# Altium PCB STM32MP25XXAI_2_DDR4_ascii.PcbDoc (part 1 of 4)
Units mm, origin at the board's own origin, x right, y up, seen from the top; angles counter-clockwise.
Board outline 172 x 137 mm, 4 copper layers (Top Layer, Signal Layer 1, Signal Layer 2, Bottom Layer), stack 1.614 mm thick; 241 components, 153 nets, 1312 pads, 924 vias.
Unrouted connection lines stored in the file: 13.
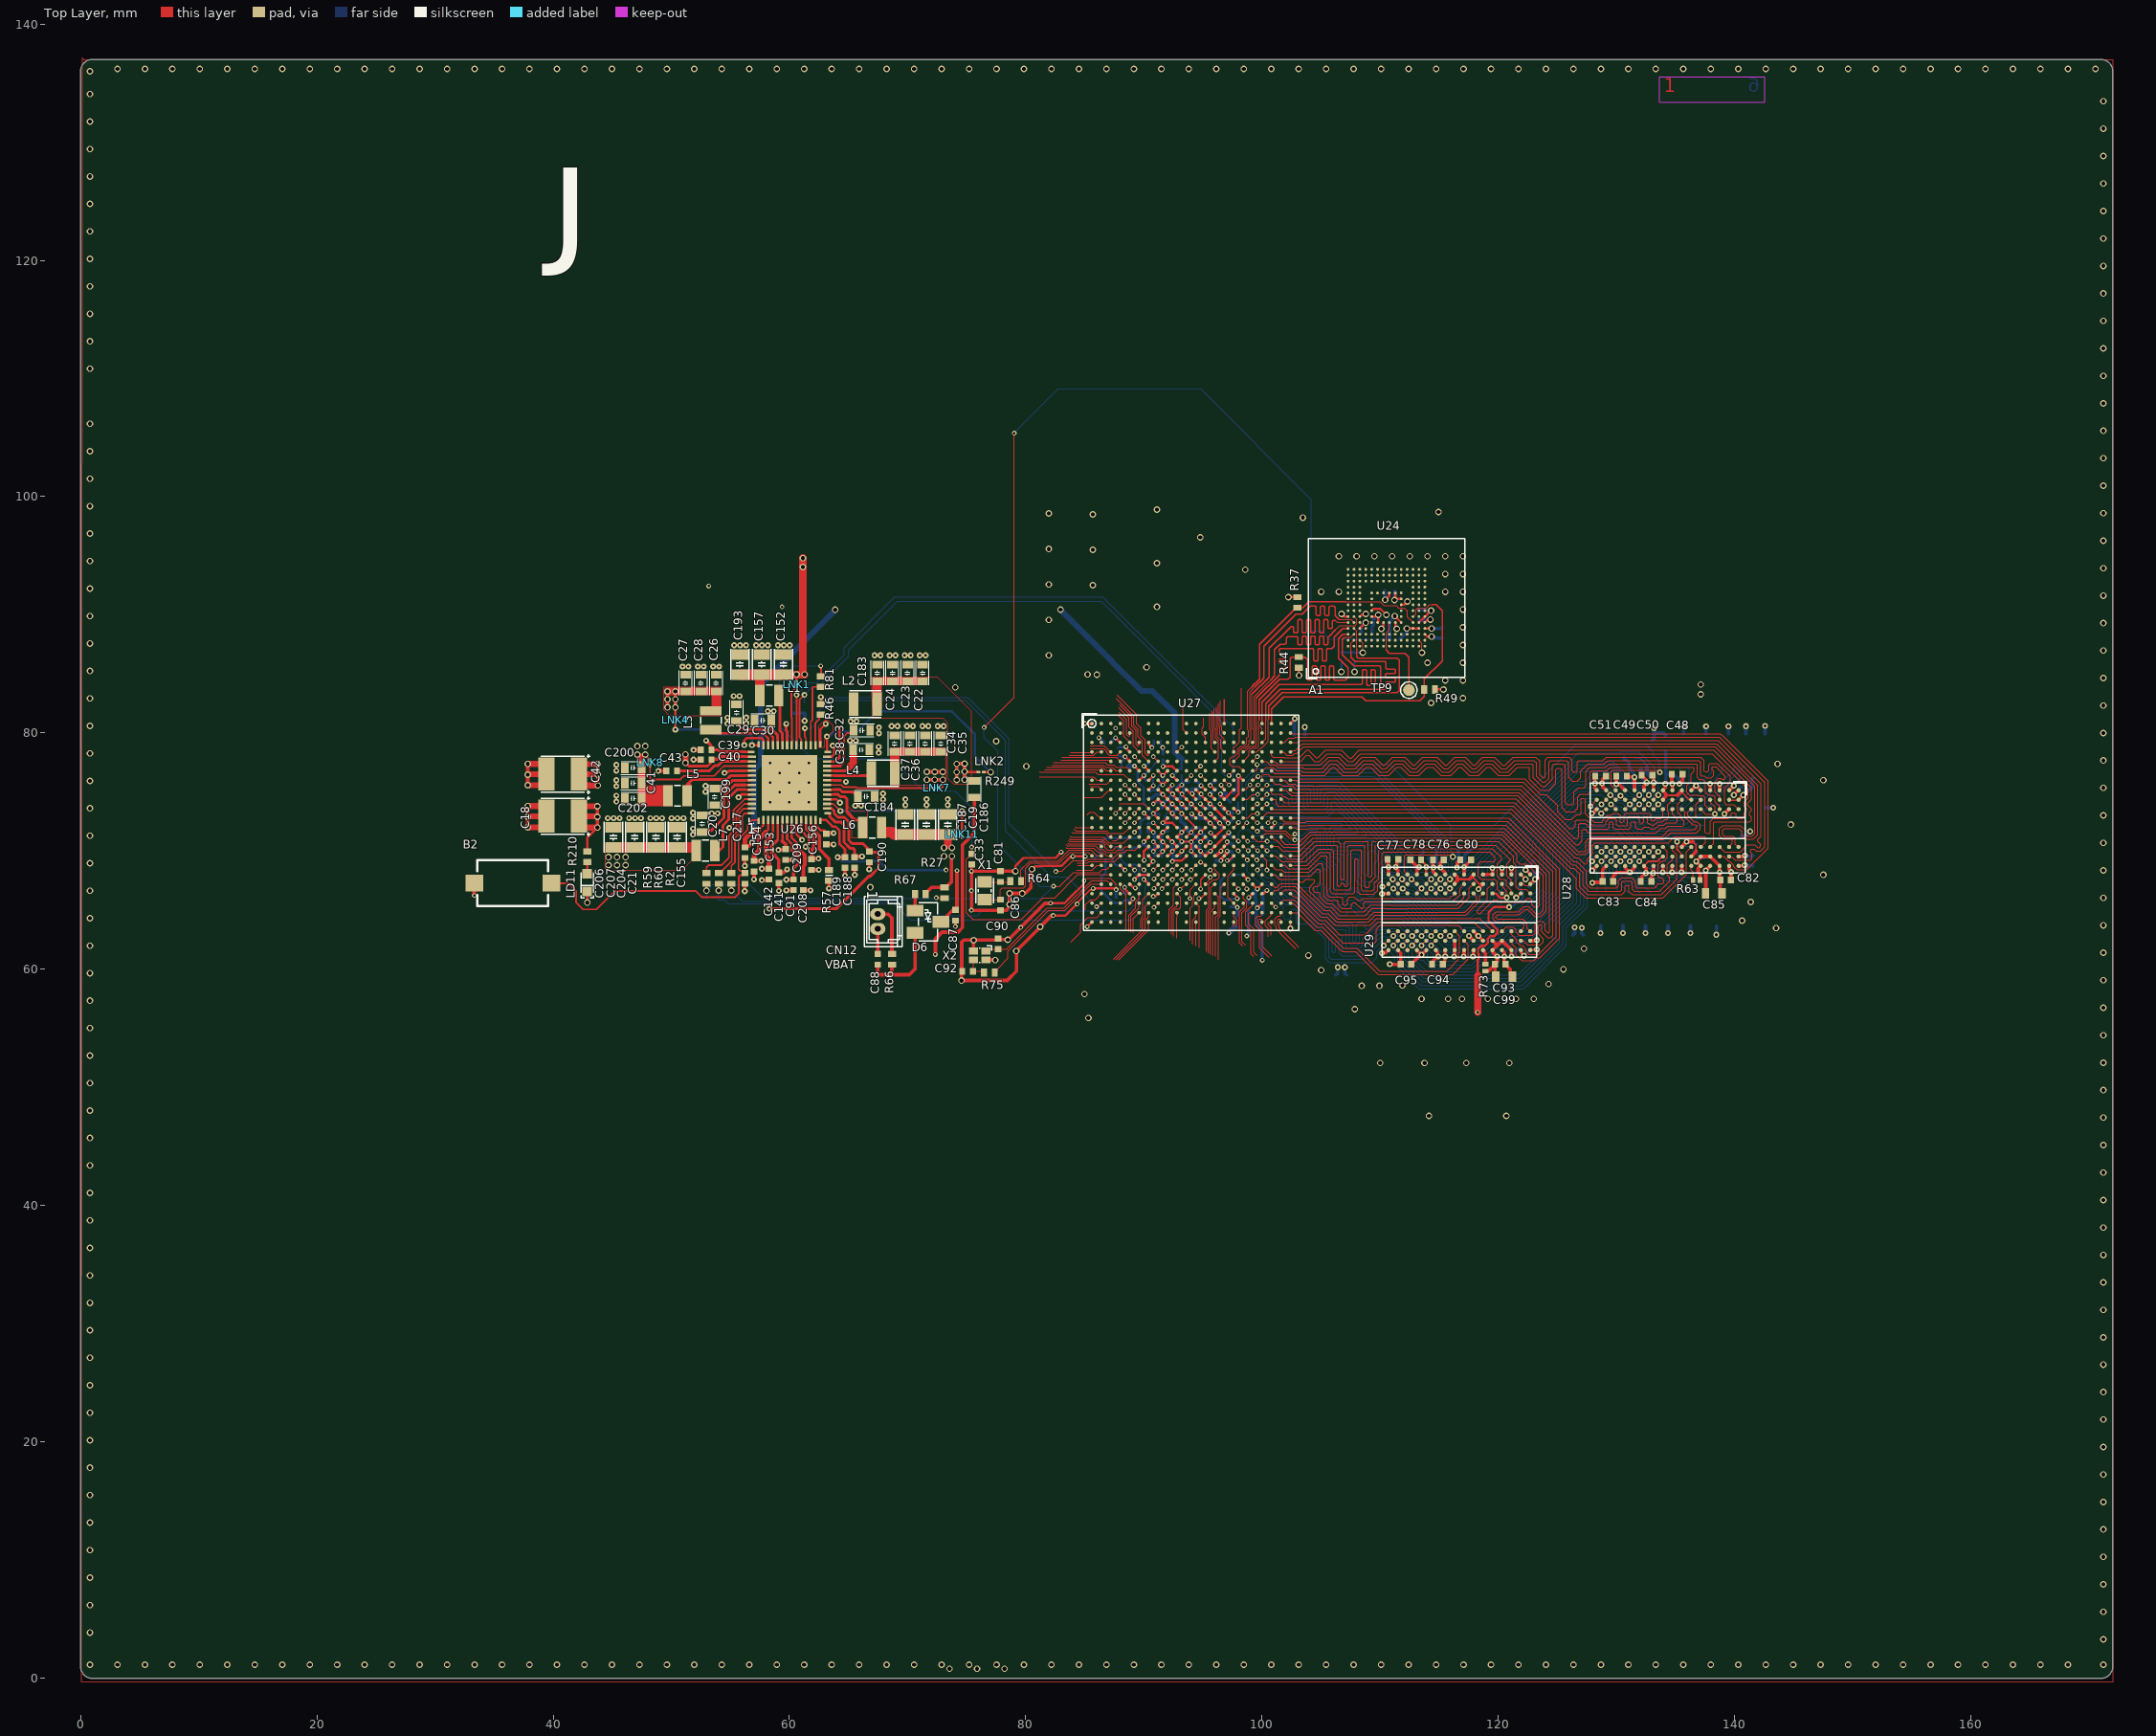
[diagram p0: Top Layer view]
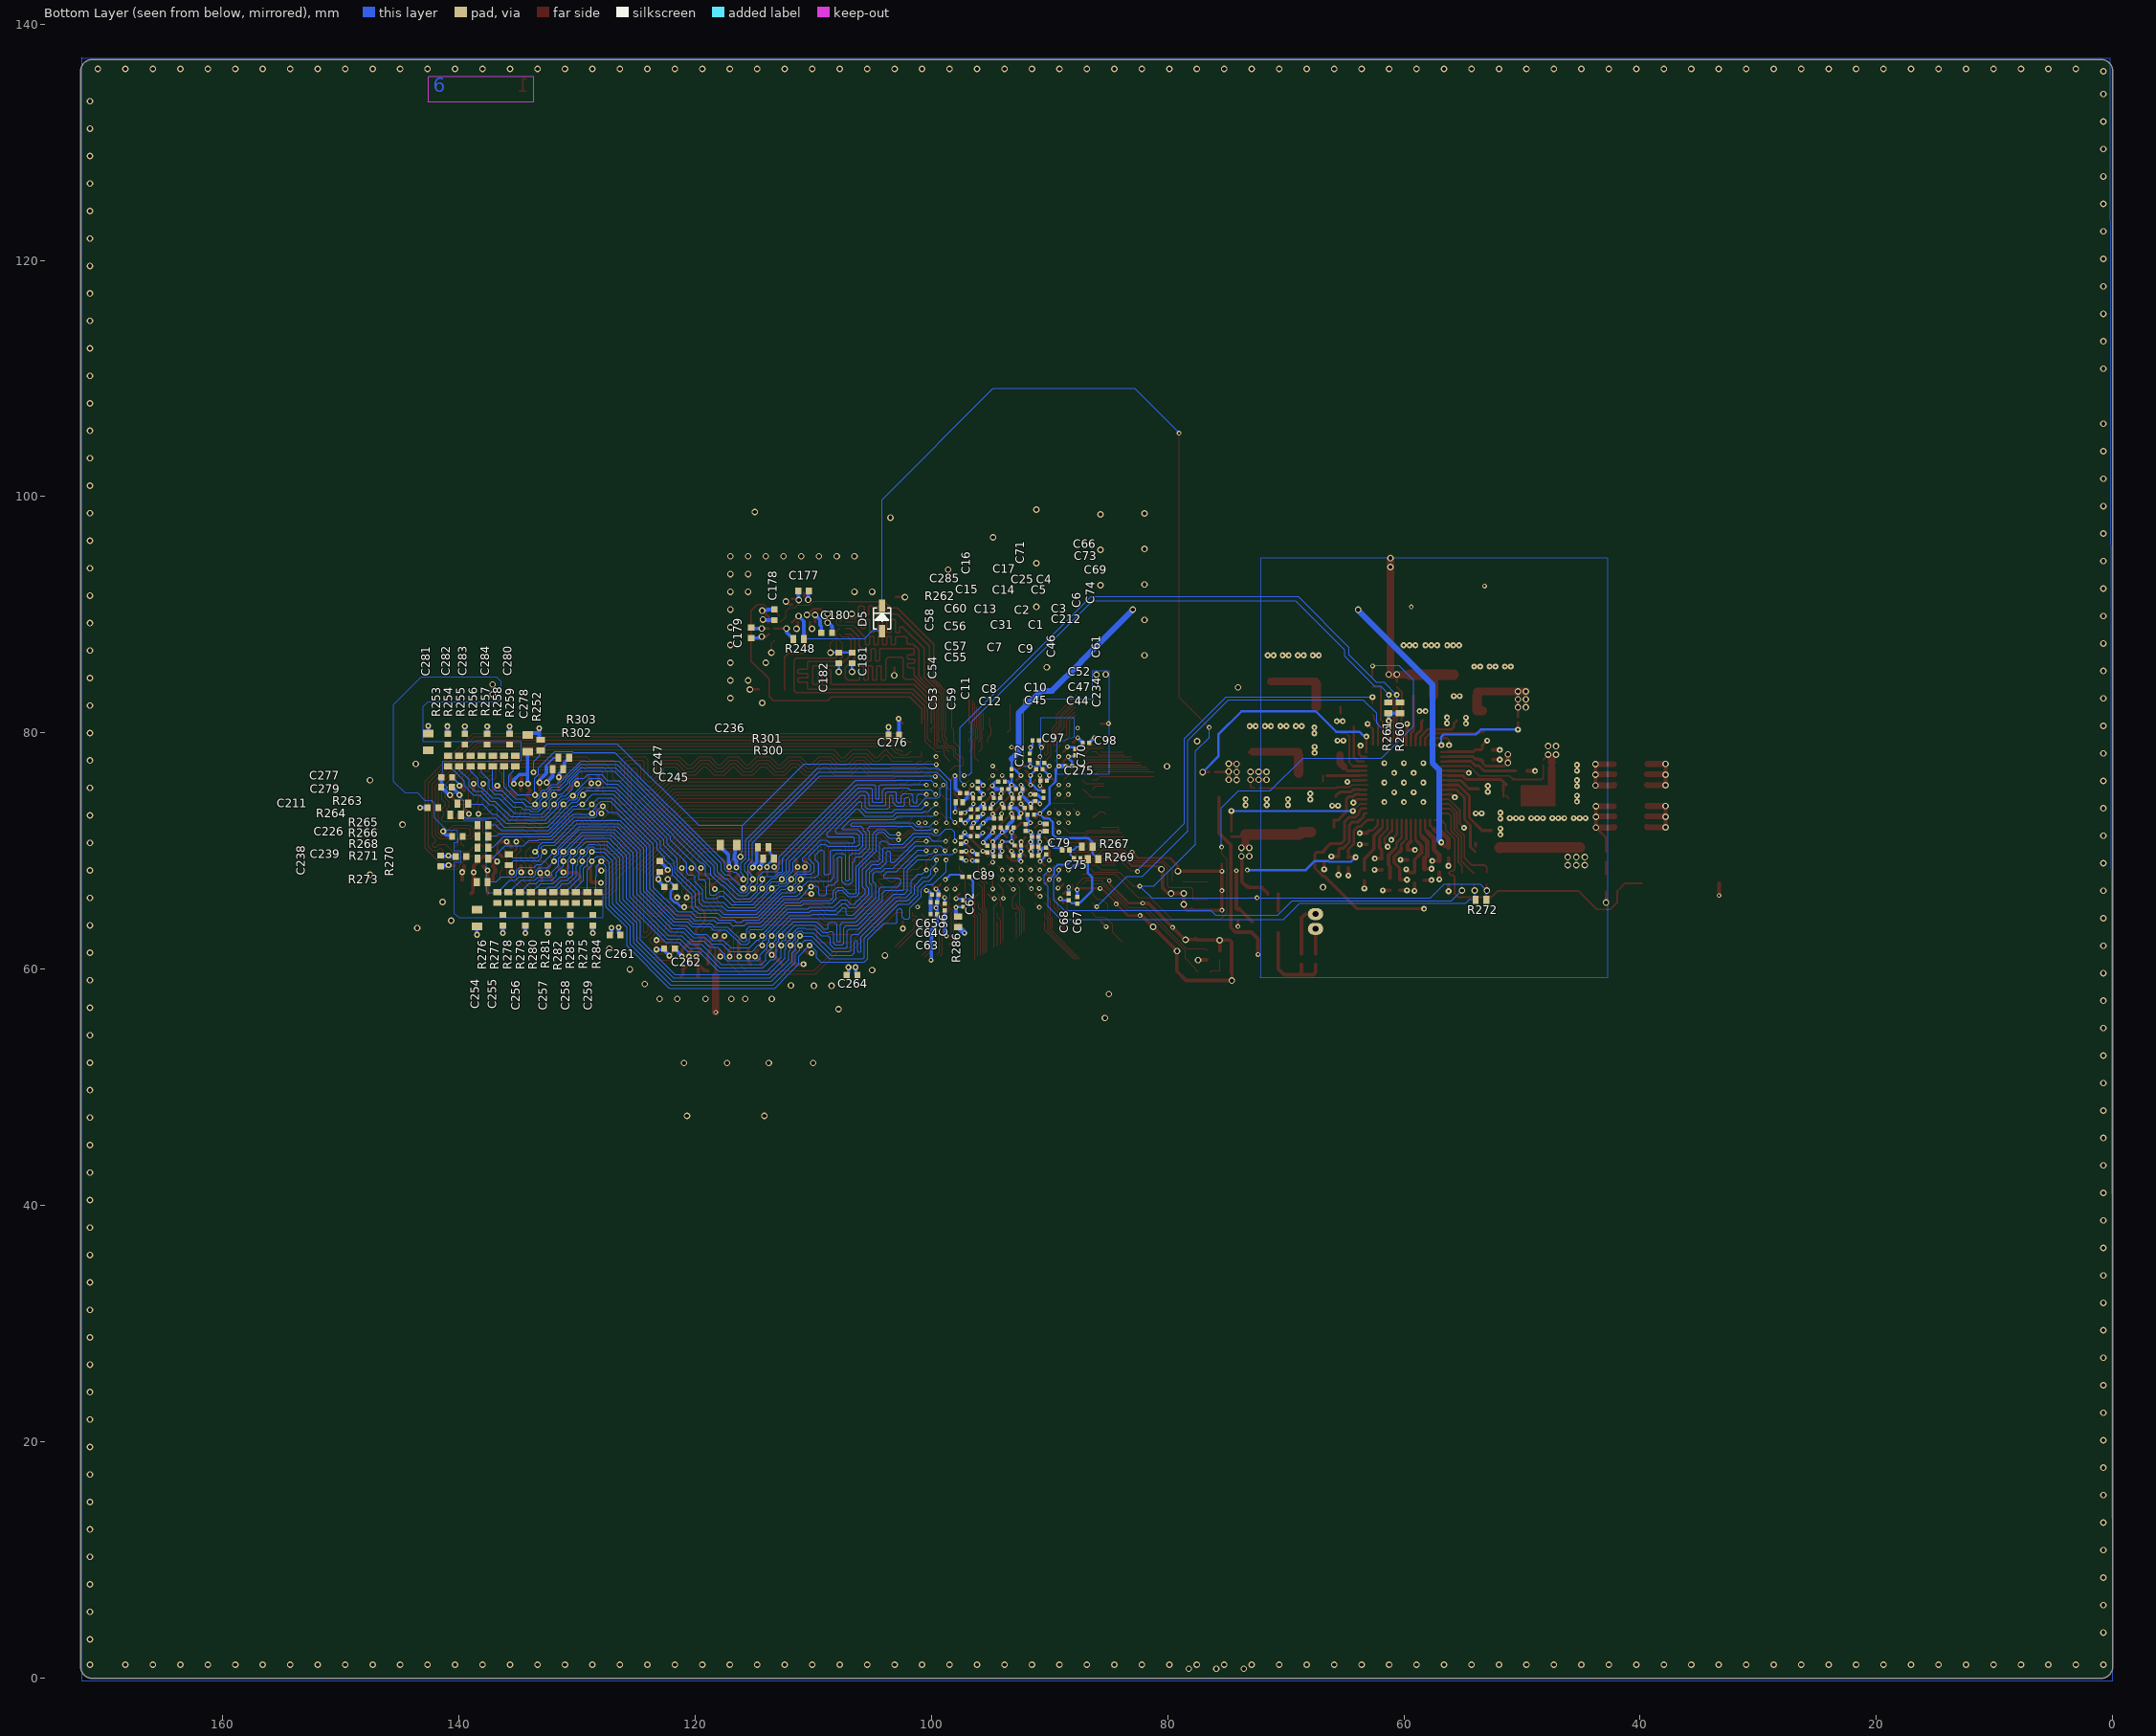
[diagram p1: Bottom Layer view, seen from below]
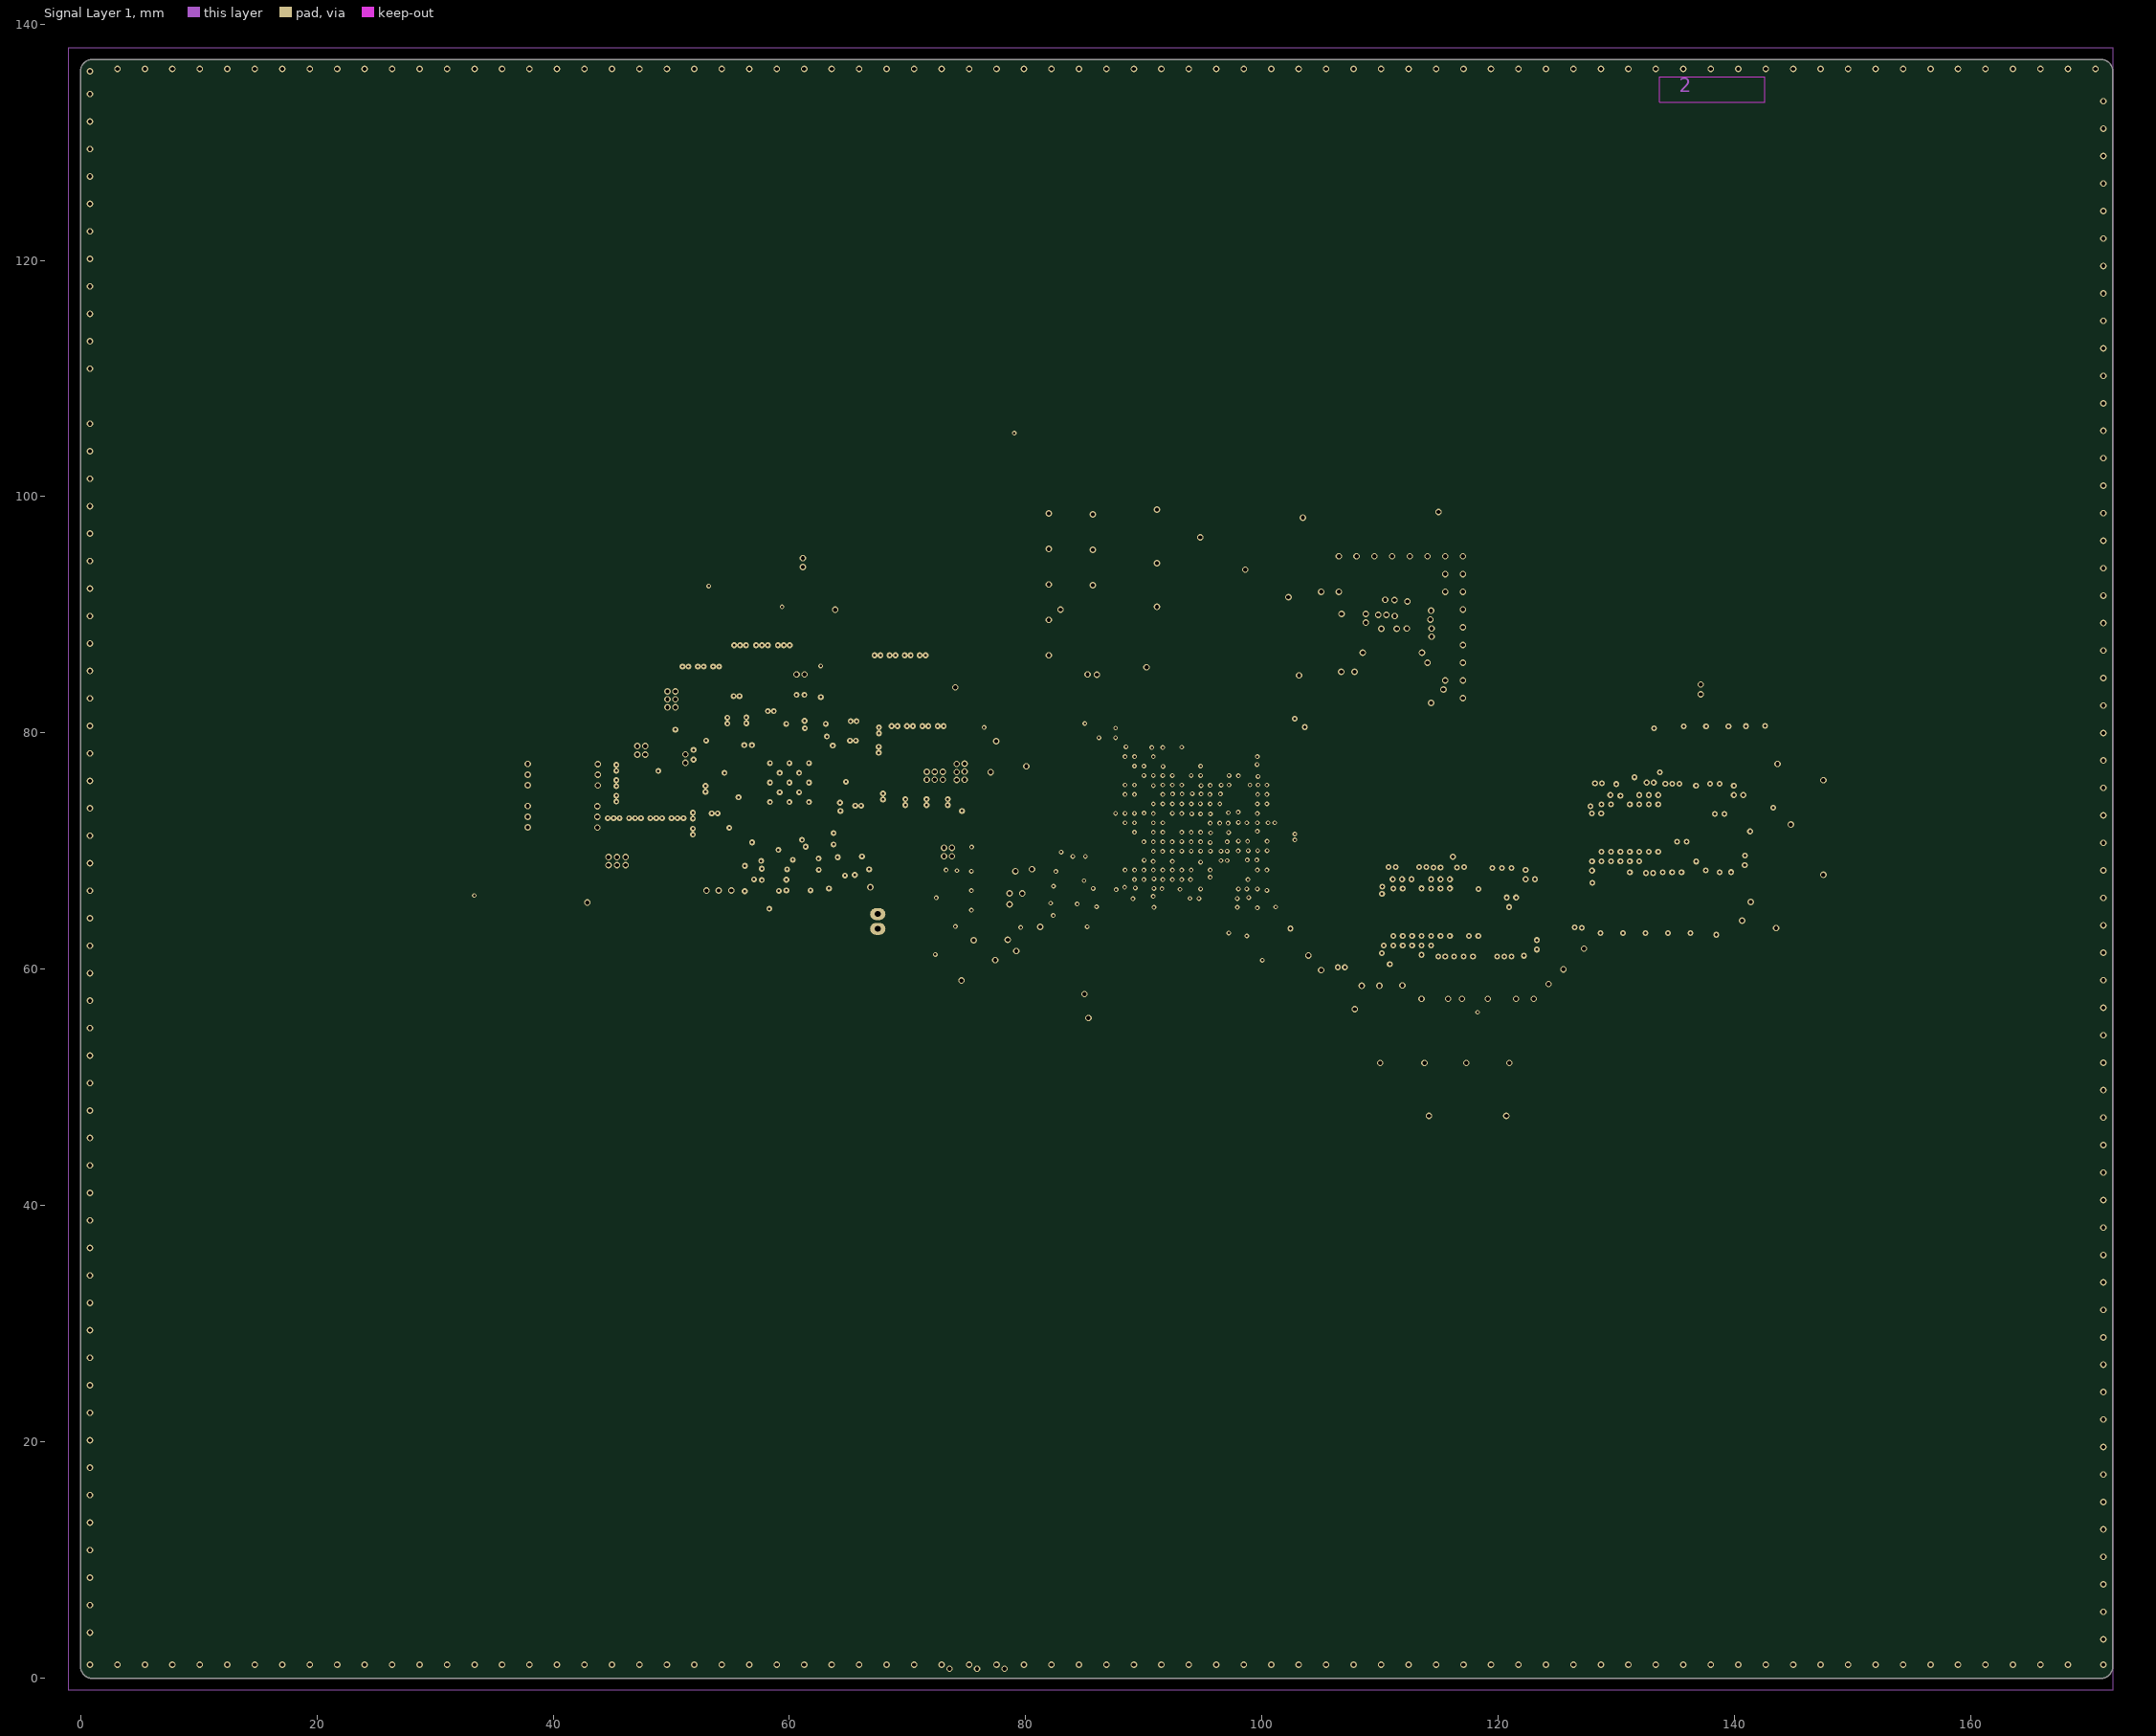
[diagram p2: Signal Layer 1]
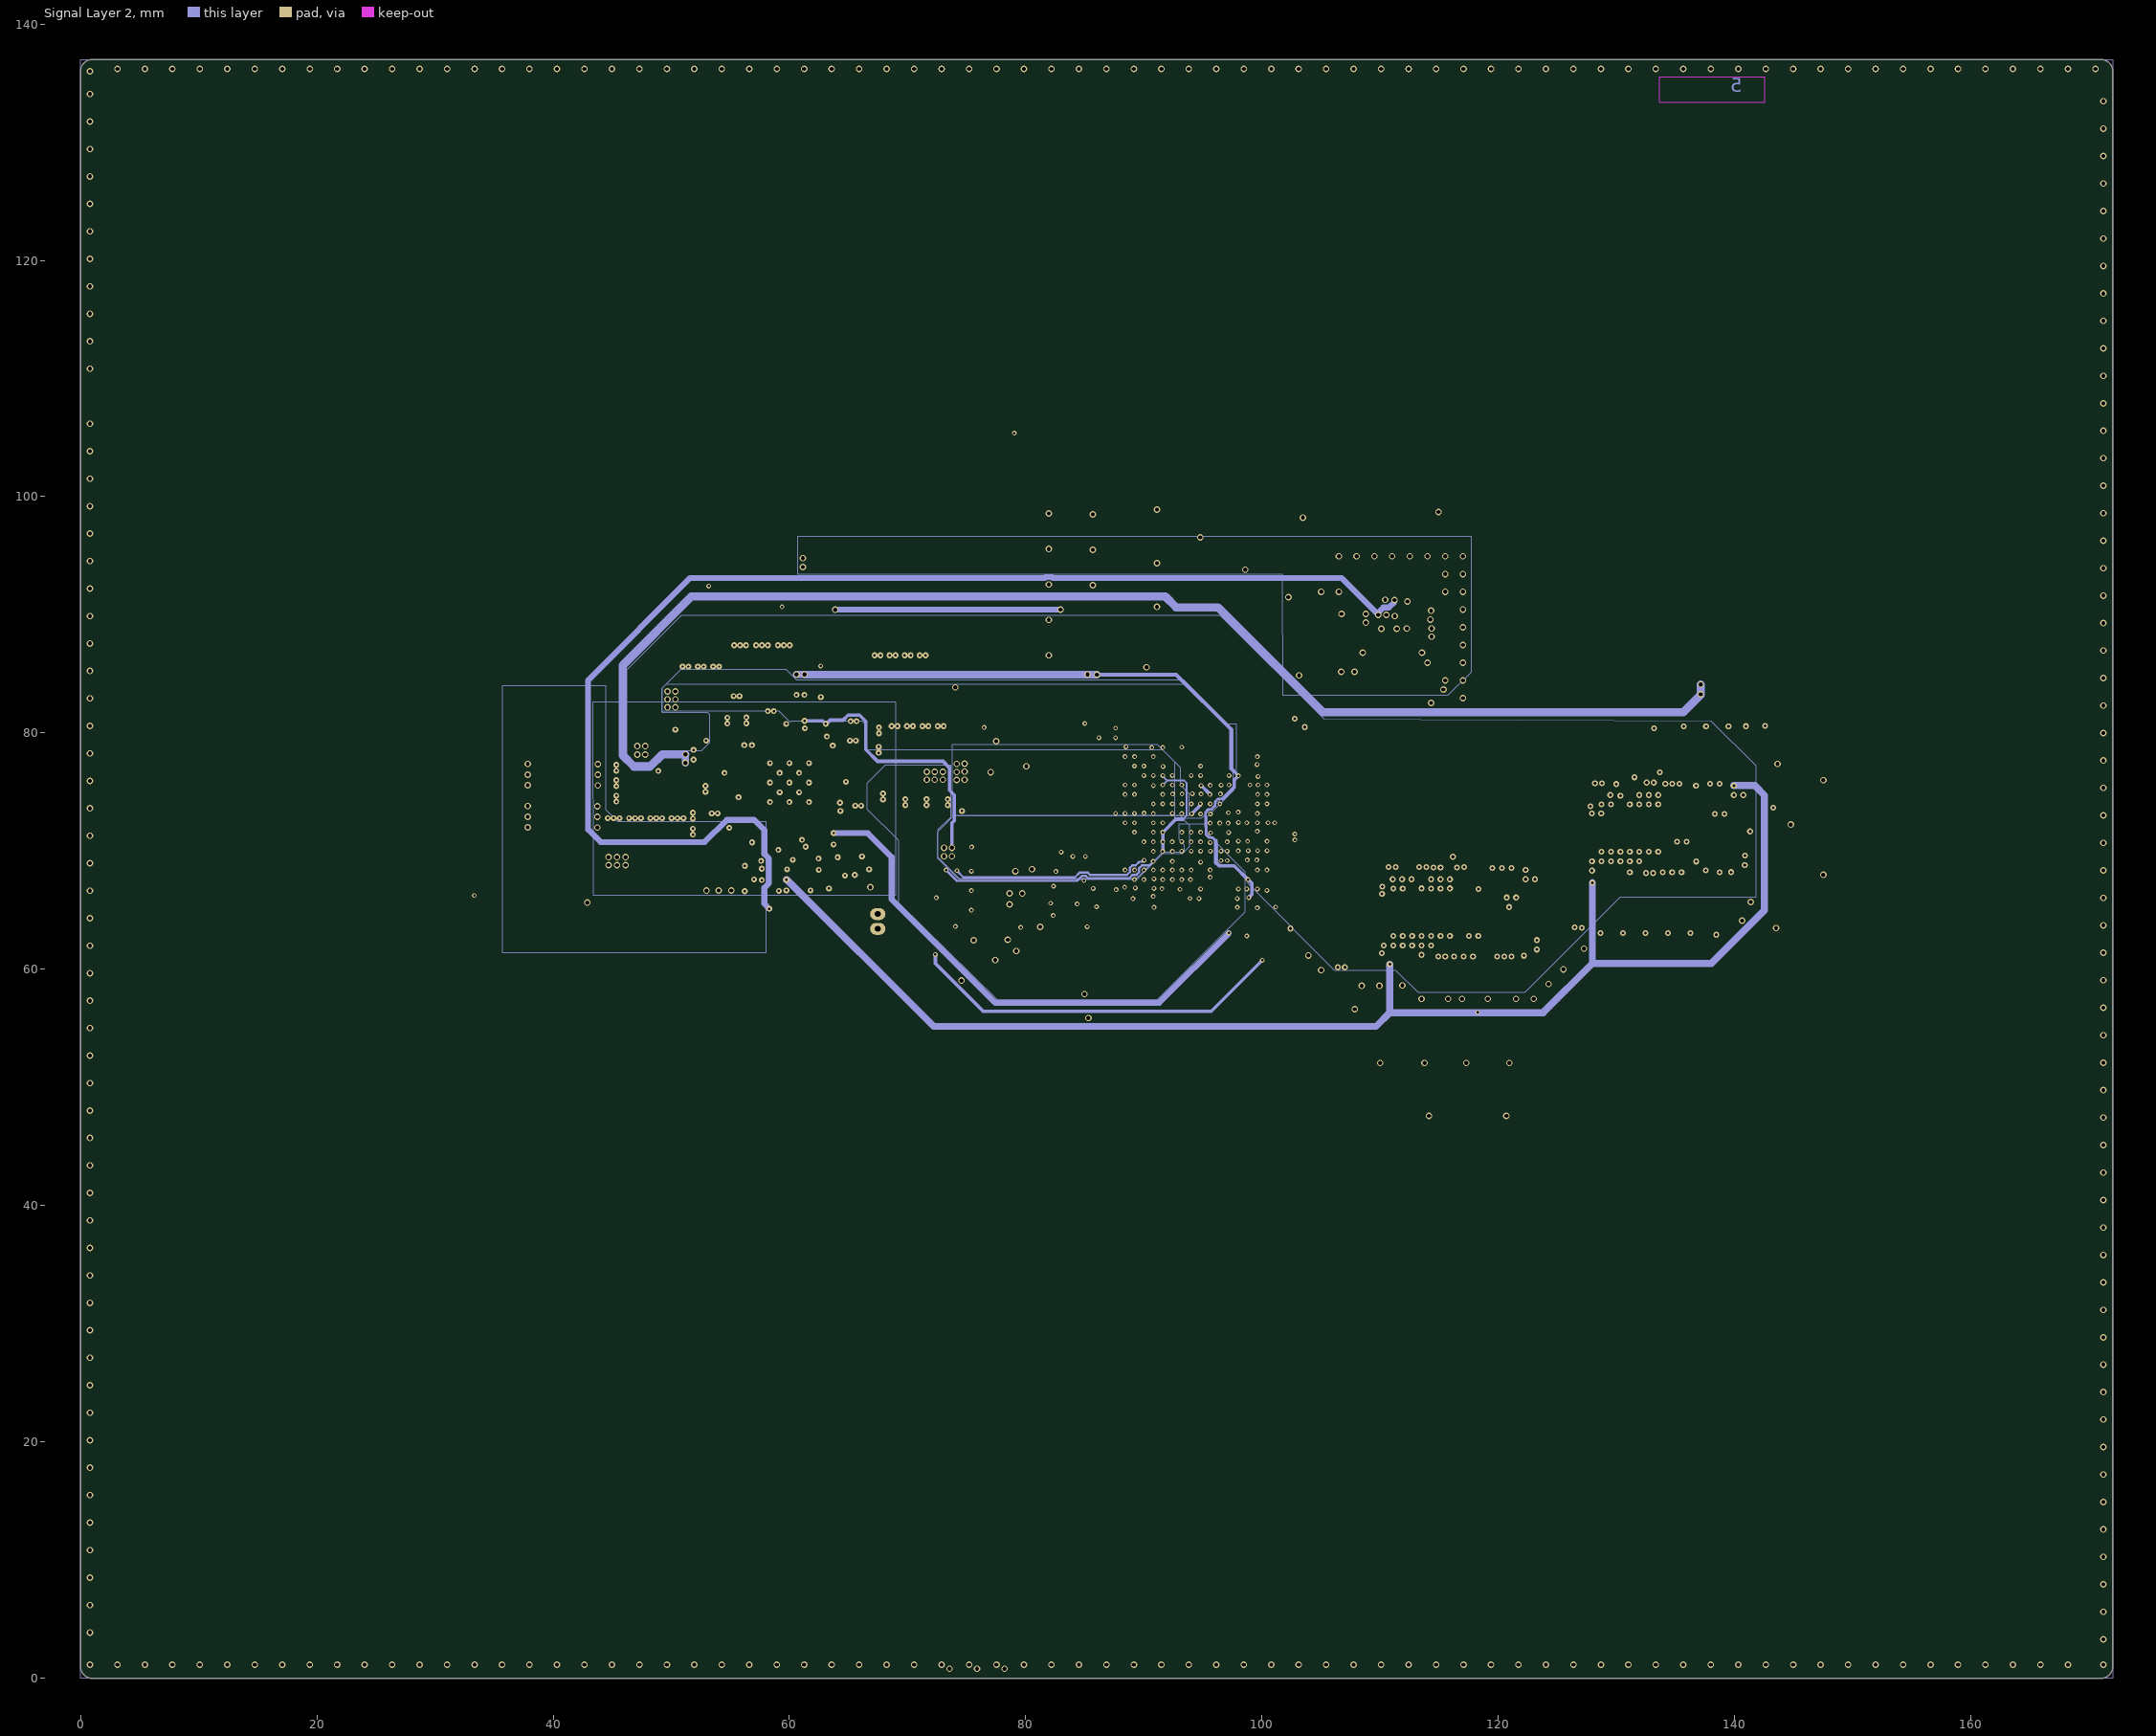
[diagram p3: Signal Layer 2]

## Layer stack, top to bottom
Top Solder: solder mask 0.025, Solder Resist, Dk 3.5
Top Layer: signal copper 0.037
Dielectric 1: prepreg 0.07, Dk 3.8
Signal Layer 1: signal copper 0.035
Dielectric 2: core 1.33, Dk 4.3
Signal Layer 2: signal copper 0.035
Dielectric 3: prepreg 0.07, Dk 3.8
Bottom Layer: signal copper 0.037
Bottom Solder: solder mask 0.025, Solder Resist, Dk 3.5

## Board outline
0,1 0,95 0,136 cw(c1,136) 1,137 171,137 cw(c171,136) 172,136 172,1 cw(c171,1) 171,0 1,0 cw(c1,1)

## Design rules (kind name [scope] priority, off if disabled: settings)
AssemblyTestPointUsage [All] p0: scope1count=1 scope1_0_kind=Board scope1_0_value=Board scope2count=1 scope2_0_kind=Board scope2_0_value=Board commentlength=0
AssemblyTestpoint [All] p0: scope1count=1 scope1_0_kind=Board scope1_0_value=Board scope2count=1 scope2_0_kind=Board scope2_0_value=Board commentlength=0
BoardOutlineClearance Silkscreen [All] p0 off: scope1count=1 scope1_0_kind=Board scope1_0_value=Board scope2count=1 scope2_0_kind=Board scope2_0_value=Board commentlength=90 gap=0 // Protel DXP Scope 1 Expression Was: OnLayer('Top Overlay') or OnLayer('Bottom Overlay')
BoardOutlineClearance [All] p0: scope1count=1 scope1_0_kind=Board scope1_0_value=Board scope2count=1 scope2_0_kind=Board scope2_0_value=Board commentlength=0 gap=0.5
BoardOutlineClearance Silkscreen [OnLayer('Top Overlay') or OnLayer('Bottom Overlay')] p1: gap=0 ignorepadtopadclearanceinfootprint=FALSE
BoardOutlineClearance [All] p2: gap=0.5 ignorepadtopadclearanceinfootprint=FALSE
Clearance Clearance_Default [All] p0: scope1count=1 scope1_0_kind=Board scope1_0_value=Board scope2count=1 scope2_0_kind=Board scope2_0_value=Board commentlength=0 gap=0.1
Clearance Clearance_Default [All] p1: gap=0.1 ignorepadtopadclearanceinfootprint=TRUE except(0: Arc-Hole Track-Hole SMDPad-Hole THPad-Hole Via-Hole Fill-Hole Poly-Hole Region-Hole Text-Hole; 0.09: Track-Track Track-SMDPad)
ComponentClearance [All] p0 off: scope1count=1 scope1_0_kind=Board scope1_0_value=Board scope2count=1 scope2_0_kind=Board scope2_0_value=Board commentlength=0 gap=0.2 collisioncheckmode=3
ComponentClearance [All] p1 off: gap=0.2 collisioncheckmode=3 verticalgap=0 showdistances=FALSE
DiffPairsRouting DiffPairsRouting_DDR_100R [All] p0 off: scope1count=1 scope1_0_kind=Board scope1_0_value=Board scope2count=1 scope2_0_kind=Board scope2_0_value=Board commentlength=78 // Protel DXP Scope 1 Expression Was: InDifferentialPairClass('DPC_DDR_100R')
DiffPairsRouting DiffPairsRouting_DDR_100R [InDifferentialPairClass('DPC_DDR_100R')] p1: maxlimit=0.16 minlimit=0.14 mostfreqgap=0.254 toplayer_mingap=0.16 toplayer_prefgap=0.16 toplayer_minwidth=0.09 toplayer_maxwidth=0.09 toplayer_prefwidth=0.09 bottomlayer_mingap=0.16 bottomlayer_prefgap=0.16 bottomlayer_minwidth=0.09 bottomlayer_maxwidth=0.09 bottomlayer_prefwidth=0.09 impedanceprofiledriven=TRUE impedanceprofileid={5106416E-43F8-41F8-8BCA-F68B3FB1C141} impedanceprofilevalue=100.000000 maxuncoupledlength=12.7
FabricationTestPointUsage [All] p0: scope1count=1 scope1_0_kind=Board scope1_0_value=Board scope2count=1 scope2_0_kind=Board scope2_0_value=Board commentlength=0 valid=0 allowmultiple=FALSE
FabricationTestpoint [All] p0: scope1count=1 scope1_0_kind=Board scope1_0_value=Board scope2count=1 scope2_0_kind=Board scope2_0_value=Board commentlength=0 side=3 testpointundercomponent=TRUE minsize=1.016 maxsize=2.54 preferedsize=1.524 minholesize=0 maxholesize=1.016 preferedholesize=0.813 testpointgrid=0.025
FanoutControl Fanout_Default [All] p0: scope1count=1 scope1_0_kind=Board scope1_0_value=Board scope2count=1 scope2_0_kind=Board scope2_0_value=Board commentlength=30 // Fanout_Default (Default Rule)
FanoutControl Fanout_Small [All] p0 off: scope1count=1 scope1_0_kind=Board scope1_0_value=Board scope2count=1 scope2_0_kind=Board scope2_0_value=Board commentlength=84 // Protel DXP Scope 1 Expression Was: (CompPinCount < 5)   Fanout_Small (Default Rule)
FanoutControl Fanout_SOIC [All] p0 off: scope1count=1 scope1_0_kind=Board scope1_0_value=Board scope2count=1 scope2_0_kind=Board scope2_0_value=Board commentlength=71 // Protel DXP Scope 1 Expression Was: IsSOIC   Fanout_SOIC (Default Rule)
FanoutControl Fanout_LCC [All] p0 off: scope1count=1 scope1_0_kind=Board scope1_0_value=Board scope2count=1 scope2_0_kind=Board scope2_0_value=Board commentlength=69 // Protel DXP Scope 1 Expression Was: IsLCC   Fanout_LCC (Default Rule)
FanoutControl Fanout_BGA [All] p0 off: scope1count=1 scope1_0_kind=Board scope1_0_value=Board scope2count=1 scope2_0_kind=Board scope2_0_value=Board commentlength=69 // Protel DXP Scope 1 Expression Was: IsBGA   Fanout_BGA (Default Rule)
FanoutControl Fanout_BGA [IsBGA] p1: bgadir=Out bgaviamode=Closest fanoutstyle=Auto fanoutdirection=Alternating viagrid=0.025 // Fanout_BGA (Default Rule)
FanoutControl Fanout_LCC [IsLCC] p2: bgadir=Out bgaviamode=Closest fanoutstyle=Auto fanoutdirection=Alternating viagrid=0.025 // Fanout_LCC (Default Rule)
FanoutControl Fanout_SOIC [IsSOIC] p3: bgadir=Out bgaviamode=Closest fanoutstyle=Auto fanoutdirection=Alternating viagrid=0.025 // Fanout_SOIC (Default Rule)
FanoutControl Fanout_Small [(CompPinCount < 5)] p4: bgadir=Out bgaviamode=Closest fanoutstyle=Auto fanoutdirection=OutThenIn viagrid=0.025 // Fanout_Small (Default Rule)
FanoutControl Fanout_Default [All] p5: bgadir=Out bgaviamode=Closest fanoutstyle=Auto fanoutdirection=Alternating viagrid=0.025 // Fanout_Default (Default Rule)
Height [All] p0: scope1count=1 scope1_0_kind=Board scope1_0_value=Board scope2count=1 scope2_0_kind=Board scope2_0_value=Board commentlength=0
HoleSize [All] p0: scope1count=1 scope1_0_kind=Board scope1_0_value=Board scope2count=1 scope2_0_kind=Board scope2_0_value=Board commentlength=0 absolutevalues=TRUE maxlimit=10 minlimit=0.025 maxpercent=80.000 minpercent=20.000
HoleSize [All] p1: absolutevalues=TRUE maxlimit=10 minlimit=0.025 maxpercent=80.000 minpercent=20.000
HoleToHoleClearance [All] p0: scope1count=1 scope1_0_kind=Board scope1_0_value=Board scope2count=1 scope2_0_kind=Board scope2_0_value=Board commentlength=0
HoleToHoleClearance [All] p1: gap=0.25 allowstackedmicrovias=TRUE
LayerPairs [All] p0: scope1count=1 scope1_0_kind=Board scope1_0_value=Board scope2count=1 scope2_0_kind=Board scope2_0_value=Board commentlength=0 enforce=TRUE
MinimumSolderMaskSliver [All] p0: scope1count=1 scope1_0_kind=Board scope1_0_value=Board scope2count=1 scope2_0_kind=Board scope2_0_value=Board commentlength=0
MinimumSolderMaskSliver [All] p1: minsoldermaskwidth=0.07
NetAntennae [All] p0: scope1count=1 scope1_0_kind=Board scope1_0_value=Board scope2count=1 scope2_0_kind=Board scope2_0_value=Board commentlength=0
PasteMaskExpansion [All] p0: scope1count=1 scope1_0_kind=Board scope1_0_value=Board scope2count=1 scope2_0_kind=Board scope2_0_value=Board commentlength=0 expansion=0
PlaneClearance [All] p0: scope1count=1 scope1_0_kind=Board scope1_0_value=Board scope2count=1 scope2_0_kind=Board scope2_0_value=Board commentlength=0 clearance=0.508
PlaneConnect [All] p0: scope1count=1 scope1_0_kind=Board scope1_0_value=Board scope2count=1 scope2_0_kind=Board scope2_0_value=Board commentlength=0 planeconnectstyle=Direct reliefexpansion=0.508 reliefentries=4 reliefconductorwidth=0.21 reliefairgap=0.21
PlaneConnect [All] p1: planeconnectstyle=Direct reliefexpansion=0.508 reliefentries=4 reliefconductorwidth=0.21 reliefairgap=0.21
PolygonConnect PolygonConnect_Default [All] p0: scope1count=1 scope1_0_kind=Board scope1_0_value=Board scope2count=1 scope2_0_kind=Board scope2_0_value=Board commentlength=0 connectstyle=Direct reliefconductorwidth=0.25 reliefentries=4 polygonreliefangle="90 Angle"
PolygonConnect PolygonConnect_Default [All] p1: connectstyle=Direct reliefconductorwidth=0.25 reliefentries=4 polygonreliefangle="90 Angle" airgapwidth=0.25
RoutingCorners [All] p0: scope1count=1 scope1_0_kind=Board scope1_0_value=Board scope2count=1 scope2_0_kind=Board scope2_0_value=Board commentlength=0 cornerstyle=45-Degree minsetback=2.54 maxsetback=2.54
RoutingLayers [All] p0: scope1count=1 scope1_0_kind=Board scope1_0_value=Board scope2count=1 scope2_0_kind=Board scope2_0_value=Board commentlength=0 top layer=Automatic mid layer 1=Automatic mid layer 4=Automatic bottom layer=Automatic
RoutingPriority [All] p0: scope1count=1 scope1_0_kind=Board scope1_0_value=Board scope2count=1 scope2_0_kind=Board scope2_0_value=Board commentlength=0
RoutingTopology [All] p0: scope1count=1 scope1_0_kind=Board scope1_0_value=Board scope2count=1 scope2_0_kind=Board scope2_0_value=Board commentlength=0 topology=Shortest
RoutingVias RoutingVias_Default [All] p0: scope1count=1 scope1_0_kind=Board scope1_0_value=Board scope2count=1 scope2_0_kind=Board scope2_0_value=Board commentlength=0 holewidth=0.15 width=0.4 viastyle="Through Hole" minholewidth=0.15 minwidth=0.4 maxholewidth=0.35 maxwidth=0.6
RoutingVias RoutingVias_Default [All] p1: holewidth=0.15 width=0.4 viastyle="Through Hole" minholewidth=0.15 minwidth=0.4 maxholewidth=0.35 maxwidth=0.6 viatemplateguid#1={BF886351-5902-4D8E-87A9-DD407FAE4AFA} viatemplateguid#2={A479BBDC-94B7-4D18-B59D-B7A18B767B5F} viatemplateguid#3={564DD7E2-F718-4BCE-8A99-5417C9FECCB6} viatemplateguid#4={BB8F4C89-420F-4EBC-9772-FD82009DE81A} viatemplateguid#5={3FF096CA-B7A5-4E0B-A50A-8B2CD18CCC19} viatemplatename#1=v50h25m30mx30 viatemplatename#2=v55h35m40mx40 viatemplatename#3=v40h20m0mx0 viatemplatename#4=v40h20m25mx25 viatemplatename#5=v50h25m0mx0
ShortCircuit ShortCircuit_Link200 [All] p0: scope1count=1 scope1_0_kind=PadClass scope1_0_value=PC_LINK200 scope2count=1 scope2_0_kind=Board scope2_0_value=Board commentlength=0 allowed=TRUE
ShortCircuit ShortCircuit_Link200 [InPadClass('PC_LINK200')] p1: allowed=TRUE
SilkToBoardRegionClearance [All] p0: scope1count=1 scope1_0_kind=Board scope1_0_value=Board scope2count=1 scope2_0_kind=Board scope2_0_value=Board commentlength=0
SilkToSilkClearance [All] p0: scope1count=1 scope1_0_kind=Board scope1_0_value=Board scope2count=1 scope2_0_kind=Board scope2_0_value=Board commentlength=0
SilkToSilkClearance [All] p1: silktosilkclearance=0.2
SilkToSolderMaskClearance [All] p0 off: scope1count=1 scope1_0_kind=Board scope1_0_value=Board scope2count=1 scope2_0_kind=Board scope2_0_value=Board commentlength=44 // Protel DXP Scope 1 Expression Was: IsPad
SilkToSolderMaskClearance [IsPad] p1: minsilkscreentomaskgap=0.015 clearancetoexposedcopper=TRUE
SolderMaskExpansion [All] p0: scope1count=1 scope1_0_kind=Board scope1_0_value=Board scope2count=1 scope2_0_kind=Board scope2_0_value=Board commentlength=0 expansion=0.1
SolderMaskExpansion [All] p1: expansion=0.1 istentingtop=FALSE
UnRoutedNet [All] p0: scope1count=1 scope1_0_kind=Board scope1_0_value=Board scope2count=1 scope2_0_kind=Board scope2_0_value=Board commentlength=0
UnpouredPolygon [All] p0: scope1count=1 scope1_0_kind=Board scope1_0_value=Board scope2count=1 scope2_0_kind=Board scope2_0_value=Board commentlength=0
ViasUnderSMD [All] p0: scope1count=1 scope1_0_kind=PadClass scope1_0_value=PC_VIAS-IN-PAD_OK scope2count=1 scope2_0_kind=Board scope2_0_value=Board commentlength=0 allowed=TRUE
ViasUnderSMD [InPadClass('PC_VIAS-IN-PAD_OK')] p1: allowed=TRUE
Width Width_Default [All] p0: scope1count=1 scope1_0_kind=NetClass scope1_0_value="All Nets" scope2count=1 scope2_0_kind=Board scope2_0_value=Board commentlength=0 maxlimit=10 minlimit=0.09 preferedwidth=0.1
Width Width_Default [InNetClass('All Nets')] p1: maxlimit=10 minlimit=0.09 preferedwidth=0.1
16 further rules are at their usual default settings.

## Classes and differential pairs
differential pair DDR_DQS3: +DDR_DQS3_P -DDR_DQS3_N
differential pair DDR_DQS2: +DDR_DQS2_P -DDR_DQS2_N
differential pair DDR_DQS1: +DDR_DQS1_P -DDR_DQS1_N
differential pair DDR_DQS0: +DDR_DQS0_P -DDR_DQS0_N
differential pair " ": +DDR_CLK_P -DDR_CLK_N

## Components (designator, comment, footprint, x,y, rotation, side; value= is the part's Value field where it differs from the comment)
B2 "SW_PUSH_SMD_2P" SWI_WE_434121025816 36.59,67.295 r0 top
C1 "Capacitor" C0201_MURATA_GRM033_H0P3 92.825,72.825 r0 bottom
C2 "Capacitor" C0201_MURATA_GRM033_H0P3 93.601,73.65 r180 bottom
C3 "Capacitor" C0201_MURATA_GRM033_H0P3 91.825,73.65 r180 bottom
C4 "Capacitor" C0201_MURATA_GRM033_H0P3 92.55,75.25 r0 bottom
C5 "Capacitor" C0201_MURATA_GRM033_H0P3 92.826,74.475 r180 bottom
C6 "Capacitor" C0201_MURATA_GRM033_H0P3 91.2,74.525 r270 bottom
C7 "Capacitor" C0201_MURATA_GRM033_H0P3 94.4,72 r0 bottom
C8 "Capacitor" C0201_MURATA_GRM033_H0P3 94.425,70.425 r180 bottom
C9 "Capacitor" C0201_MURATA_GRM033_H0P3 93.3,72 r180 bottom
C10 "Capacitor" C0201_MURATA_GRM033_H0P3 92.675,70.48 r0 bottom
C11 "Capacitor" C0201_MURATA_GRM033_H0P3 95.25,70.175 r270 bottom
C12 "Capacitor" C0201_MURATA_GRM033_H0P3 94.425,69.575 r180 bottom
C13 "Capacitor" C0201_MURATA_GRM033_H0P3 95.232,73.625 r0 bottom
C14 "Capacitor" C0201_MURATA_GRM033_H0P3 94.425,74.48 r180 bottom
C15 "Capacitor" C0201_MURATA_GRM033_H0P3 96.175,74.475 r180 bottom
C16 "Capacitor" C0201_MURATA_GRM033_H0P3 96.075,75.6 r90 bottom
C17 "Capacitor" C0201_MURATA_GRM033_H0P3 94.05,75.875 r0 bottom
C18 "Cap_POL_TANA" CPOL_TCJ-B_1210_H210 40.812,72.961 r180 top
C19 "Capacitor" C0805 71.6,72.25 r270 top
C20 "Capacitor" C0603 52.6,72.325 r270 top
C21 "Capacitor" C0805 50.5,71.173 r270 top
C22 "Capacitor" C0603 71.275,85.075 r270 top
C23 "Capacitor" C0603 70,85.075 r270 top
C24 "Capacitor" C0603 68.725,85.075 r270 top
C25 "Capacitor" C0201_MURATA_GRM033_H0P3 93.75,75.25 r0 bottom
C26 "Capacitor" C0603 53.8,84.225 r270 top
C27 "Capacitor" C0603 51.2,84.225 r270 top
C28 "Capacitor" C0603 52.5,84.225 r270 top
C29 "Capacitor" C0603 55.525,81.725 r270 top
C30 "Capacitor" C0603 57.75,81.075 r0 top
C31 "Capacitor" C0201_MURATA_GRM033_H0P3 94.4,72.775 r180 bottom
C32 "Capacitor" C0603 66.125,80.225 r180 top
C33 "Capacitor" C0402 75.425,69.325 r90 top
C34 "Capacitor" C0603 71.5,79.1 r270 top
C35 "Capacitor" C0603 72.8,79.1 r270 top
C36 "Capacitor" C0603 70.2,79.1 r270 top
C37 "Capacitor" C0603 68.9,79.1 r270 top
C38 "Capacitor" C0603 66.075,78.575 r180 top
C39 "Capacitor" C0402 52.945,78.575 r0 top
C40 "Capacitor" C0402 52.945,77.75 r0 top
C41 "Capacitor" C0603 46.775,75.75 r0 top
C42 "Cap_POL_TANA" CPOL_TCJ-B_1210_H210 40.812,76.523 r180 top
C43 "Capacitor" C0402 50.035,76.8 r0 top
C44 "Capacitor" C0201_MURATA_GRM033_H0P3 91.2,69.6 r180 bottom
C45 "Capacitor" C0201_MURATA_GRM033_H0P3 92.8,69.6 r0 bottom
C46 "Capacitor" C0201_MURATA_GRM033_H0P3 92.025,72 r270 bottom
C47 "Capacitor" C0201_MURATA_GRM033_H0P3 91.2,70.388 r180 bottom
C48 "Capacitor" C0402 135.125,76.5 r0 top
C49 "Capacitor" C0402 130.425,76.35 r0 top
C50 "Capacitor" C0402 132.575,76.425 r180 top
C51 "Capacitor" C0402 128.65,76.35 r0 top
C52 "Capacitor" C0201_MURATA_GRM033_H0P3 91.2,71.2 r0 bottom
C53 "Capacitor" C0201_MURATA_GRM033_H0P3 97.45,69.675 r270 bottom
C54 "Capacitor" C0201_MURATA_GRM033_H0P3 97.475,70.9 r90 bottom
C55 "Capacitor" C0201_MURATA_GRM033_H0P3 96.375,71.275 r180 bottom
C56 "Capacitor" C0201_MURATA_GRM033_H0P3 96.349,72.875 r180 bottom
C57 "Capacitor" C0201_MURATA_GRM033_H0P3 96.301,71.974 r0 bottom
C58 "Capacitor" C0201_MURATA_GRM033_H0P3 97.5,72.925 r90 bottom
C59 "Capacitor" C0201_MURATA_GRM033_H0P3 96.1,69.45 r90 bottom
C60 "Capacitor" C0201_MURATA_GRM033_H0P3 96.356,73.524 r0 bottom
C61 "Capacitor" C0201_H0P5 90.317,71.988 r90 bottom
C62 "Capacitor" C0201_MURATA_GRM033_H0P3 97.3,65.575 r270 bottom
C63 "Capacitor" C0201_MURATA_GRM033_H0P3 99.775,64.675 r180 bottom
C64 "Capacitor" C0201_MURATA_GRM033_H0P3 99.775,65.675 r180 bottom
C65 "Capacitor" C0201_MURATA_GRM033_H0P3 99.65,66.325 r180 bottom
C66 "Capacitor" C0201_MURATA_GRM033_H0P3 90.7,77.475 r180 bottom
C67 "Capacitor" C0201_MURATA_GRM033_H0P3 87.63,65.845 r270 bottom
C68 "Capacitor" C0201_MURATA_GRM033_H0P3 88.375,66.125 r270 bottom
C69 "Capacitor" C0201_MURATA_GRM033_H0P3 90.48,75.97 r0 bottom
C70 "Capacitor" C0201_MURATA_GRM033_H0P3 87.8,78.375 r90 bottom
C71 "Capacitor" C0201_MURATA_GRM033_H0P3 93.201,76.675 r90 bottom
C72 "Capacitor" C0201_MURATA_GRM033_H0P3 91.675,77.975 r270 bottom
C73 "Capacitor" C0201_MURATA_GRM033_H0P3 90.85,76.925 r0 bottom
C74 "Capacitor" C0201_MURATA_GRM033_H0P3 90.5,74.775 r90 bottom
C75 "Capacitor" C0201_MURATA_GRM033_H0P3 87.65,69.425 r0 bottom
C76 "Capacitor" C0402 114.925,69.275 r180 top
C77 "Capacitor" C0402 111.075,69.3 r0 top
C78 "Capacitor" C0402 113,69.275 r0 top
C79 "Capacitor" C0201_H0P5 88.6,70.125 r180 bottom
C80 "Capacitor" C0402 117.225,69.275 r180 top
C81 "Capacitor" C0402 77.85,67.85 r90 top
C82 "Capacitor" C0402 139.225,67.55 r0 top
C83 "Capacitor" C0402 129.275,67.45 r180 top
C84 "Capacitor" C0402 132.5,67.45 r180 top
C85 "Capacitor" C0603 138.225,66.425 r180 top
C86 "Capacitor" C0402 77.85,65.45 r270 top
C87 "" C0402 74.05,64.575 r90 top
C88 "Capacitor" C0402 67.475,60.85 r270 top
C89 "Capacitor" C0201_MURATA_GRM033_H0P3 97.075,67.825 r0 bottom
C90 "Capacitor" C0402 77.65,62.15 r270 top
C91 "Capacitor" C0402 60.345,67.16 r270 top
C92 "Capacitor" C0402 75.075,59.825 r180 top
C93 "Capacitor" C0402 120.15,60.425 r0 top
C94 "Capacitor" C0402 114.844,60.422 r180 top
C95 "Capacitor" C0402 112.175,60.425 r180 top
C96 "Capacitor" C0201_MURATA_GRM033_H0P3 98.85,65.275 r90 bottom
C97 "Capacitor" C0201_MURATA_GRM033_H0P3 91.15,79.375 r180 bottom
C98 "Capacitor" C0201_MURATA_GRM033_H0P3 86.9,79.175 r0 bottom
C99 "Capacitor" C0603 120.475,59.4 r0 top
C141 "Capacitor" C0402 59.1,67.75 r270 top
C142 "Capacitor" C0402 58.275,68.06 r270 top
C152 "Capacitor" C0805 59.5,85.8 r270 top
C153 "Capacitor" C0402 59.675,69.72 r90 top
C154 "Capacitor" C0402 57,68.725 r90 top
C155 "Capacitor" C0402 56.227,67.695 r90 top
C156 "Capacitor" C0402 63.125,71.02 r90 top
C157 "Capacitor" C0805 57.65,85.8 r270 top
C177 "Capacitor" C0402 110.8,92.025 r0 bottom
C178 "Capacitor" C0402 113.275,90 r270 bottom
C179 "Capacitor" C0402 115.225,88.475 r270 bottom
C180 "Capacitor" C0402 108.85,88.475 r0 bottom
C181 "Capacitor" C0402 106.7,86.35 r90 bottom
C182 "Capacitor" C0402 107.825,86.35 r90 bottom
C183 "Capacitor" C0603 67.45,85.075 r270 top
C184 "Capacitor" C0603 66.497,74.625 r180 top
C186 "Capacitor" C0805 73.4,72.25 r270 top
C187 "Capacitor" C0805 69.8,72.25 r270 top
C188 "Capacitor" C0402 65.525,69.04 r90 top
C189 "Capacitor" C0402 64.7,69.04 r90 top
C190 "Capacitor" C0402 66.75,69.515 r270 top
C193 "Capacitor" C0805 55.8,85.8 r270 top
C199 "Capacitor" C0603 53.675,74.6 r90 top
C200 "Capacitor" C0603 46.775,77.05 r0 top
C202 "Capacitor" C0603 46.775,74.45 r0 top
C204 "Capacitor" C0805 48.7,71.173 r270 top
C206 "Capacitor" C0805 45.1,71.173 r270 top
C207 "Capacitor" C0805 46.9,71.173 r270 top
C208 "Capacitor" C0402 61.17,67.16 r270 top
C209 "Capacitor" C0402 61.85,68.87 r90 top
C211 "Capacitor" C0402 142.175,73.675 r180 bottom
C212 "Capacitor" C0201_MURATA_GRM033_H0P3 91.585,73.1 r180 bottom
C217 "Capacitor" C0402 56.225,69.87 r270 top
C226 "Capacitor" C0402 140.1,71.25 r180 bottom
C234 "Capacitor" C0201_MURATA_GRM033_H0P3 90.275,70.01 r270 bottom
C236 "Capacitor" C0603 117.15,70.525 r180 bottom
C238 "Capacitor" C0402 141.525,69.175 r270 bottom
C239 "Capacitor" C0402 139.8,69.55 r180 bottom
C245 "Capacitor" C0402 122.125,66.975 r180 bottom
C247 "Capacitor" C0402 122.975,68.7 r90 bottom
C254 "Capacitor" C0603 138.45,64.35 r90 bottom
C255 "Capacitor" C0402 136.25,64.15 r90 bottom
C256 "Capacitor" C0402 134.35,64.15 r90 bottom
C257 "Capacitor" C0402 132.45,64.15 r90 bottom
C258 "Capacitor" C0402 130.55,64.15 r90 bottom
C259 "Capacitor" C0402 128.65,64.15 r90 bottom
C261 "Capacitor" C0402 126.75,62.9 r180 bottom
C262 "Capacitor" C0402 122.15,61.75 r0 bottom
C264 "Capacitor" C0402 106.7,59.525 r180 bottom
C275 "Capacitor" C0201_MURATA_GRM033_H0P3 88.35,77.2 r0 bottom
C276 "Capacitor" C0402 103.17,79.846 r0 bottom
C277 "Capacitor" C0402 141,76.25 r180 bottom
C278 "Capacitor" C0603 134.15,79.125 r270 bottom
C279 "Capacitor" C0402 141.025,75.425 r180 bottom
C280 "Capacitor" C0402 135.675,79.475 r270 bottom
C281 "Capacitor" C0603 142.575,79.25 r270 bottom
C282 "Capacitor" C0402 140.925,79.475 r270 bottom
C283 "Capacitor" C0402 139.475,79.475 r270 bottom
C284 "Capacitor" C0402 137.575,79.475 r270 bottom
C285 "Capacitor" C0201_MURATA_GRM033_H0P3 97.28,74.91 r0 bottom
CN12 "" CON_MOLEX_53047-0210 67.475,64.05 r270 top
D5 "BAT60JFILM" DIO_SOD323 104.175,89.7 r90 bottom
D6 "DIODE_3P_DUAL_COMMON_CATHODE" DIO_SOT23 71.725,64.025 r270 top
L1 "Inductor" IND_2016_MURATA_LQM2MPN2R2NG0 58.295,83.175 r180 top
L2 "Inductor" IND_2520_TOKO_DFE252012P 66.415,82.45 r0 top
L3 "Inductor" IND_2016_MURATA_LQM2MPN2R2NG0 53.35,81.075 r90 top
L4 "Inductor" IND_2520_TOKO_DFE252012P 67.925,76.6 r0 top
L5 "Inductor" IND_2016_MURATA_LQM2MPN2R2NG0 50.525,74.7 r180 top
L6 "Inductor" IND_2016_MURATA_LQM2MPN2R2NG0 67,72 r0 top
L7 "Inductor" IND_2016_MURATA_LQM2MPN2R2NG0 52.9,70.05 r180 top
LD11 "LED_green" LED_0603_OSRAM_LG-Q396-PS-35_GREEN_1A2K_H0P4 42.887,67.327 r270 top
LNK1 "link_200" LINK200 60.6,84.123 r0 top
LNK2 "link_200" LINK200 76.219,76.687 r90 top
LNK4 "link_200" LINK200 50.35,81.125 r180 top
LNK7 "link_200" LINK200 72.45,75.35 r270 top
LNK8 "link_200" LINK200 48.2,77.498 r0 top
LNK11 "link_200" LINK200 74.6,71.44 r180 top
R2 "" R0402 55.08,67.695 r90 top
R27 "Resistor" R0402 73.125,66.475 r90 top
R37 "Resistor" R0402 102.975,91.05 r90 top
R44 "Resistor" R0402 103.1,85.978 r270 top
R46 "" R0402 62.65,81.998 r270 top
R49 "Resistor" R0402 114.175,83.685 r0 top
R57 "" R0402 63.35,67.95 r90 top
R59 "" R0402 52.98,67.695 r90 top
R60 "" R0402 54.03,67.695 r90 top
R63 "Resistor" R0201_H0P23 136.775,67.55 r180 top
R64 "" R0402 79.15,67.45 r180 top
R66 "Resistor" R0402 68.675,60.845 r270 top
R67 "Resistor" R0402 71.075,66.375 r0 top
R73 "Resistor" R0201_H0P23 118.9,60.15 r90 top
R75 "" R0402 76.925,59.725 r0 top
R81 "" R0402 62.663,84.348 r270 top
R210 "Resistor" R0402 42.887,69.52 r270 top
R248 "Resistor" R0402 111.225,87.95 r0 bottom
R249 "Resistor" R0603 75.65,75.25 r270 top
R252 "Resistor" R0402 133.05,78.975 r270 bottom
R253 "Resistor" R0402 140.9,77.625 r90 bottom
R254 "Resistor" R0402 139.95,77.625 r90 bottom
R255 "Resistor" R0402 139,77.625 r90 bottom
R256 "Resistor" R0402 138.05,77.625 r90 bottom
R257 "Resistor" R0402 137.1,77.625 r90 bottom
R258 "Resistor" R0402 136.15,77.625 r90 bottom
R259 "Resistor" R0402 135.2,77.625 r90 bottom
R260 "Resistor" R0402 60.33,82.13 r270 bottom
R261 "Resistor" R0402 61.305,82.13 r270 bottom
R262 "Resistor" R0201_H0P23 97.624,74.149 r0 bottom
R263 "Resistor" R0402 139.65,74.025 r0 bottom
R264 "Resistor" R0402 140.25,73.075 r0 bottom
R265 "Resistor" R0402 137.95,72.2 r0 bottom
R266 "Resistor" R0402 137.95,71.25 r0 bottom
R267 "" R0402 86.8,70.375 r180 bottom
R268 "Resistor" R0402 137.95,70.3 r0 bottom
R269 "" R0402 86.304,69.315 r0 bottom
R270 "Resistor" R0402 135.75,69.275 r90 bottom
R271 "Resistor" R0402 137.95,69.35 r0 bottom
R272 "Resistor" R0402 53.475,65.879 r0 bottom
R273 "Resistor" R0402 138,67.375 r0 bottom
R275 "Resistor" R0402 129.12,66.08 r270 bottom
R276 "Resistor" R0402 136.725,66.075 r270 bottom
R277 "Resistor" R0402 135.775,66.075 r270 bottom
R278 "Resistor" R0402 134.825,66.075 r270 bottom
R279 "Resistor" R0402 133.875,66.075 r270 bottom
R280 "Resistor" R0402 132.925,66.075 r270 bottom
R281 "Resistor" R0402 131.975,66.075 r270 bottom
R282 "Resistor" R0402 131.025,66.075 r270 bottom
R283 "Resistor" R0402 130.075,66.075 r270 bottom
R284 "Resistor" R0402 128.175,66.075 r270 bottom
R286 "" R0402 97.725,64.025 r90 bottom
R300 "Resistor" R0402 113.775,69.375 r0 bottom
R301 "Resistor" R0402 114.225,70.325 r180 bottom
R302 "Resistor" R0402 131.6,76.95 r0 bottom
R303 "Resistor" R0402 131.1,77.9 r180 bottom
TP9 "Test Point" TP_SMD_1MM 112.43,83.629 r90 top
U24 "eMMC_THGBMTG5D1LBAIL" ICC_P-WFBGA153_13X11P5_P050 110.525,90.6 r0 top locked
U26 "STPMIC25APQR" ICC_QFN56-EPAD_6P5X6P5_P040 60,75.8 r90 top
U27 "STM32MP257FAI3" ICC_LFBGA436_18X18_P080_H1P70_STM32MP257_CODE-B0D1 94,72.4 r0 top locked
U28 "MT40A1G16TB-062E IT:F" ICC_FBGA96_TB_7P5X13_P080 134.325,71.95 r270 top locked
U29 "MT40A1G16TB-062E IT:F" ICC_FBGA96_TB_7P5X13_P080 116.7,64.825 r270 top locked
X1 "XTAL_2_PINS" CRY_NX2012SA_2P 76.525,66.65 r270 top
X2 "XTAL_4_PINS" CRY_NX1612SA_4P 76.098,61.176 r180 top

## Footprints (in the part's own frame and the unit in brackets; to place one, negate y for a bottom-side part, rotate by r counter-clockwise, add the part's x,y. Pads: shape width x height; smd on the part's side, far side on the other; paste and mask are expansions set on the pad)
C0201_H0P5 [mm] "MCD-01534"
  rect 0.4x0.5 smd mask+0: 1(-0.3,0) 2(0.3,0)
C0201_MURATA_GRM033_H0P3 [mm] "GRM033R60J105ME11"
  rect 0.35x0.35 smd mask+0: 1(-0.275,0) 2(0.275,0)
C0402 [mm]
  rect 0.51x0.56 smd mask+0: 1(-0.45,0) 2(0.45,0)
C0603 [mm]
  rect 0.64x0.89 smd mask+0: 1(-0.7,0) 2(0.7,0)
  silkscreen extent -1.05,-0.55 1.02,0.55
C0805 [mm]
  rect 0.9x1.4 smd mask+0: 1(-0.85,0) 2(0.85,0)
  silkscreen extent -1.3,-0.77 1.3,0.77
CON_MOLEX_53047-0210 [mm]
  oval 1x1.3 hole 0.5 mask+0: 1(-0.625,0) 2(0.625,0)
  silkscreen extent -2.12,-1.15 2.13,2.05
CPOL_TCJ-B_1210_H210 [mm] "MCD-01791"
  rect 1.35x2.8 smd mask+0: 1(-1.375,0) 2(1.375,0)
  silkscreen extent -2.33,-1.68 1.85,1.68
CRY_NX1612SA_4P [mm] "MCD-02262"
  rect 0.75x0.6 smd mask+0: 1(-0.525,-0.375) 2(0.525,-0.375) 3(0.525,0.375) 4(-0.525,0.375)
  silkscreen extent -1.02,-0.8 0.03,0.6
CRY_NX2012SA_2P [mm]
  rect 1x1.25 smd mask+0: 1(-0.75,0) 2(0.75,0)
  silkscreen extent -1.05,-0.75 1.05,0.75
DIO_SOD323 [mm]
  rect 1.06x0.54 smd mask+0: 1(-1.07,0) 2(1.07,0)
  silkscreen extent -0.9,-0.72 0.9,0.72
DIO_SOT23 [mm]
  rect 1x1.4 smd mask+0: 1(-0.95,-1.1) 2(0.95,-1.1) 3(0,1.1)
  silkscreen extent -1.63,-0.82 1.63,0.82
ICC_FBGA96_TB_7P5X13_P080 [mm] "MCD-03523"
  round 0.35 smd mask+0: A1(-3.2,6) A2(-2.4,6) A3(-1.6,6) A7(1.6,6) A8(2.4,6) A9(3.2,6) B1(-3.2,5.2) B2(-2.4,5.2) B3(-1.6,5.2) B7(1.6,5.2) B8(2.4,5.2) B9(3.2,5.2) C1(-3.2,4.4) C2(-2.4,4.4) C3(-1.6,4.4) C7(1.6,4.4) C8(2.4,4.4) C9(3.2,4.4) D1(-3.2,3.6) D2(-2.4,3.6) D3(-1.6,3.6) D7(1.6,3.6) D8(2.4,3.6) D9(3.2,3.6) E1(-3.2,2.8) E2(-2.4,2.8) E3(-1.6,2.8) E7(1.6,2.8) E8(2.4,2.8) E9(3.2,2.8) F1(-3.2,2) F2(-2.4,2) F3(-1.6,2) F7(1.6,2) F8(2.4,2) F9(3.2,2) G1(-3.2,1.2) G2(-2.4,1.2) G3(-1.6,1.2) G7(1.6,1.2) G8(2.4,1.2) G9(3.2,1.2) H1(-3.2,0.4) H2(-2.4,0.4) H3(-1.6,0.4) H7(1.6,0.4) H8(2.4,0.4) H9(3.2,0.4) J1(-3.2,-0.4) J2(-2.4,-0.4) J3(-1.6,-0.4) J7(1.6,-0.4) J8(2.4,-0.4) J9(3.2,-0.4) K1(-3.2,-1.2) K2(-2.4,-1.2) K3(-1.6,-1.2) K7(1.6,-1.2) K8(2.4,-1.2) K9(3.2,-1.2) L1(-3.2,-2) L2(-2.4,-2) L3(-1.6,-2) L7(1.6,-2) L8(2.4,-2) L9(3.2,-2) M1(-3.2,-2.8) M2(-2.4,-2.8) M3(-1.6,-2.8) M7(1.6,-2.8) M8(2.4,-2.8) M9(3.2,-2.8) N1(-3.2,-3.6) N2(-2.4,-3.6) N3(-1.6,-3.6) N7(1.6,-3.6) N8(2.4,-3.6) N9(3.2,-3.6) P1(-3.2,-4.4) P2(-2.4,-4.4) P3(-1.6,-4.4) P7(1.6,-4.4) P8(2.4,-4.4) P9(3.2,-4.4) R1(-3.2,-5.2) R2(-2.4,-5.2) R3(-1.6,-5.2) R7(1.6,-5.2) R8(2.4,-5.2) R9(3.2,-5.2) T1(-3.2,-6) T2(-2.4,-6) T3(-1.6,-6) T7(1.6,-6) T8(2.4,-6) T9(3.2,-6)
  silkscreen extent -3.93,-6.55 3.8,6.68
ICC_LFBGA436_18X18_P080_H1P70_STM32MP257_CODE-B0D1 [mm] "MCD02000"
  round 0.3 smd paste+0.025 mask+0: A1(-8.4,8.4) A2(-7.6,8.4) A3(-6.8,8.4) A4(-6,8.4) A7(-3.6,8.4) A8(-2.8,8.4) A11(-0.4,8.4) A12(0.4,8.4) A15(2.8,8.4) A16(3.6,8.4) A19(6,8.4) A20(6.8,8.4) A21(7.6,8.4) A22(8.4,8.4) AA1(-8.4,-7.6) AA2(-7.6,-7.6) AA3(-6.8,-7.6) AA4(-6,-7.6) AA6(-4.4,-7.6) AA7(-3.6,-7.6) AA8(-2.8,-7.6) AA10(-1.2,-7.6) AA11(-0.4,-7.6) AA12(0.4,-7.6) AA14(2,-7.6) AA15(2.8,-7.6) AA16(3.6,-7.6) AA18(5.2,-7.6) AA19(6,-7.6) AA20(6.8,-7.6) AA21(7.6,-7.6) AA22(8.4,-7.6) AB1(-8.4,-8.4) AB2(-7.6,-8.4) AB3(-6.8,-8.4) AB4(-6,-8.4) AB7(-3.6,-8.4) AB8(-2.8,-8.4) AB11(-0.4,-8.4) AB12(0.4,-8.4) AB15(2.8,-8.4) AB16(3.6,-8.4) AB19(6,-8.4) AB20(6.8,-8.4) AB21(7.6,-8.4) AB22(8.4,-8.4) B1(-8.4,7.6) B2(-7.6,7.6) B3(-6.8,7.6) B4(-6,7.6) B5(-5.2,7.6) B7(-3.6,7.6) B8(-2.8,7.6) B9(-2,7.6) B11(-0.4,7.6) B12(0.4,7.6) B13(1.2,7.6) B15(2.8,7.6) B16(3.6,7.6) B17(4.4,7.6) B19(6,7.6) B20(6.8,7.6) B21(7.6,7.6) B22(8.4,7.6) C1(-8.4,6.8) C2(-7.6,6.8) C3(-6.8,6.8) C4(-6,6.8) C5(-5.2,6.8) C6(-4.4,6.8) C7(-3.6,6.8) C8(-2.8,6.8) C9(-2,6.8) C10(-1.2,6.8) C11(-0.4,6.8) C12(0.4,6.8) C13(1.2,6.8) C14(2,6.8) C15(2.8,6.8) C16(3.6,6.8) C17(4.4,6.8) C18(5.2,6.8) C19(6,6.8) C20(6.8,6.8) C21(7.6,6.8) C22(8.4,6.8) D1(-8.4,6) D2(-7.6,6) D3(-6.8,6) D4(-6,6) D5(-5.2,6) D6(-4.4,6) D7(-3.6,6) D8(-2.8,6) D9(-2,6) D10(-1.2,6) D11(-0.4,6) D12(0.4,6) D13(1.2,6) D14(2,6) D15(2.8,6) D16(3.6,6) D17(4.4,6) D18(5.2,6) D19(6,6) D20(6.8,6) D21(7.6,6) D22(8.4,6) E3(-6.8,5.2) E4(-6,5.2) E5(-5.2,5.2) E6(-4.4,5.2) E7(-3.6,5.2) E8(-2.8,5.2) E9(-2,5.2) E10(-1.2,5.2) E11(-0.4,5.2) E12(0.4,5.2) E13(1.2,5.2) E14(2,5.2) E15(2.8,5.2) E16(3.6,5.2) E17(4.4,5.2) E18(5.2,5.2) E19(6,5.2) E20(6.8,5.2) E21(7.6,5.2) F2(-7.6,4.4) F3(-6.8,4.4) F4(-6,4.4) F5(-5.2,4.4) F6(-4.4,4.4) F7(-3.6,4.4) F8(-2.8,4.4) F9(-2,4.4) F10(-1.2,4.4) F11(-0.4,4.4) F12(0.4,4.4) F13(1.2,4.4) F14(2,4.4) F15(2.8,4.4) F16(3.6,4.4) F17(4.4,4.4) F18(5.2,4.4) F19(6,4.4) F20(6.8,4.4) G1(-8.4,3.6) G2(-7.6,3.6) G3(-6.8,3.6) G4(-6,3.6) G5(-5.2,3.6) G6(-4.4,3.6) G7(-3.6,3.6) G8(-2.8,3.6) G9(-2,3.6) G10(-1.2,3.6) G11(-0.4,3.6) G12(0.4,3.6) G13(1.2,3.6) G14(2,3.6) G15(2.8,3.6) G16(3.6,3.6) G17(4.4,3.6) G18(5.2,3.6) G19(6,3.6) G20(6.8,3.6) G21(7.6,3.6) G22(8.4,3.6) H1(-8.4,2.8) H2(-7.6,2.8) H3(-6.8,2.8) H4(-6,2.8) H5(-5.2,2.8) H6(-4.4,2.8) H7(-3.6,2.8) H8(-2.8,2.8) H9(-2,2.8) H10(-1.2,2.8) H11(-0.4,2.8) H12(0.4,2.8) H13(1.2,2.8) H14(2,2.8) H15(2.8,2.8) H16(3.6,2.8) H17(4.4,2.8) H18(5.2,2.8) H19(6,2.8) H20(6.8,2.8) H21(7.6,2.8) H22(8.4,2.8) J3(-6.8,2) J4(-6,2) J5(-5.2,2) J6(-4.4,2) J7(-3.6,2) J8(-2.8,2) J9(-2,2) J10(-1.2,2) J11(-0.4,2) J12(0.4,2) J13(1.2,2) J14(2,2) J15(2.8,2) J16(3.6,2) J17(4.4,2) J18(5.2,2) J19(6,2) J20(6.8,2) J21(7.6,2) K2(-7.6,1.2) K3(-6.8,1.2) K4(-6,1.2) K5(-5.2,1.2) K6(-4.4,1.2) K7(-3.6,1.2) K8(-2.8,1.2) K9(-2,1.2) K10(-1.2,1.2) K11(-0.4,1.2) K12(0.4,1.2) K13(1.2,1.2) K14(2,1.2) K15(2.8,1.2) K16(3.6,1.2) K17(4.4,1.2) K18(5.2,1.2) K19(6,1.2) K20(6.8,1.2) L1(-8.4,0.4) L2(-7.6,0.4) L3(-6.8,0.4) L4(-6,0.4) L5(-5.2,0.4) L6(-4.4,0.4) L7(-3.6,0.4) L8(-2.8,0.4) L9(-2,0.4) L10(-1.2,0.4) L11(-0.4,0.4) L12(0.4,0.4) L13(1.2,0.4) L14(2,0.4) L15(2.8,0.4) L16(3.6,0.4) L17(4.4,0.4) L18(5.2,0.4) L19(6,0.4) L20(6.8,0.4) L21(7.6,0.4) L22(8.4,0.4) M1(-8.4,-0.4) M2(-7.6,-0.4) M3(-6.8,-0.4) M4(-6,-0.4) M5(-5.2,-0.4) M6(-4.4,-0.4) M7(-3.6,-0.4) M8(-2.8,-0.4) M9(-2,-0.4) M10(-1.2,-0.4) M11(-0.4,-0.4) M12(0.4,-0.4) M13(1.2,-0.4) M14(2,-0.4) M15(2.8,-0.4) M16(3.6,-0.4) M17(4.4,-0.4) M18(5.2,-0.4) M19(6,-0.4) M20(6.8,-0.4) M21(7.6,-0.4) M22(8.4,-0.4) N3(-6.8,-1.2) N4(-6,-1.2) N5(-5.2,-1.2) N6(-4.4,-1.2) N7(-3.6,-1.2) N8(-2.8,-1.2) N9(-2,-1.2) N10(-1.2,-1.2) N11(-0.4,-1.2) N12(0.4,-1.2) N13(1.2,-1.2) N14(2,-1.2) N15(2.8,-1.2) N16(3.6,-1.2) N17(4.4,-1.2) N18(5.2,-1.2) N19(6,-1.2) N20(6.8,-1.2) N21(7.6,-1.2) P2(-7.6,-2) P3(-6.8,-2) P4(-6,-2) P5(-5.2,-2) P6(-4.4,-2) P7(-3.6,-2) P8(-2.8,-2) P9(-2,-2) P10(-1.2,-2) P11(-0.4,-2) P12(0.4,-2) P13(1.2,-2) P14(2,-2) P15(2.8,-2) P16(3.6,-2) P17(4.4,-2) P18(5.2,-2) P19(6,-2) P20(6.8,-2) R1(-8.4,-2.8) R2(-7.6,-2.8) R3(-6.8,-2.8) R4(-6,-2.8) R5(-5.2,-2.8) R6(-4.4,-2.8) R7(-3.6,-2.8) R8(-2.8,-2.8) R9(-2,-2.8) R10(-1.2,-2.8) R11(-0.4,-2.8) R12(0.4,-2.8) R13(1.2,-2.8) R14(2,-2.8) R15(2.8,-2.8) R16(3.6,-2.8) R17(4.4,-2.8) R18(5.2,-2.8) R19(6,-2.8) R20(6.8,-2.8) R21(7.6,-2.8) R22(8.4,-2.8) T1(-8.4,-3.6) T2(-7.6,-3.6) T3(-6.8,-3.6) T4(-6,-3.6) T5(-5.2,-3.6) T6(-4.4,-3.6) T7(-3.6,-3.6) T8(-2.8,-3.6) T9(-2,-3.6) T10(-1.2,-3.6) T11(-0.4,-3.6) T12(0.4,-3.6) T13(1.2,-3.6) T14(2,-3.6) T15(2.8,-3.6) T16(3.6,-3.6) T17(4.4,-3.6) T18(5.2,-3.6) T19(6,-3.6) T20(6.8,-3.6) T21(7.6,-3.6) T22(8.4,-3.6) U3(-6.8,-4.4) U4(-6,-4.4) U5(-5.2,-4.4) U6(-4.4,-4.4) U7(-3.6,-4.4) U8(-2.8,-4.4) U9(-2,-4.4) U10(-1.2,-4.4) U11(-0.4,-4.4) U12(0.4,-4.4) U13(1.2,-4.4) U14(2,-4.4) U15(2.8,-4.4) U16(3.6,-4.4) U17(4.4,-4.4) U18(5.2,-4.4) U19(6,-4.4) U20(6.8,-4.4) U21(7.6,-4.4) V2(-7.6,-5.2) V3(-6.8,-5.2) V4(-6,-5.2) V5(-5.2,-5.2) V6(-4.4,-5.2) V7(-3.6,-5.2) V8(-2.8,-5.2) V9(-2,-5.2) V10(-1.2,-5.2) V11(-0.4,-5.2) V12(0.4,-5.2) V13(1.2,-5.2) V14(2,-5.2) V15(2.8,-5.2) V16(3.6,-5.2) V17(4.4,-5.2) V18(5.2,-5.2) V19(6,-5.2) V20(6.8,-5.2) W1(-8.4,-6) W2(-7.6,-6) W3(-6.8,-6) W4(-6,-6) W5(-5.2,-6) W6(-4.4,-6) W7(-3.6,-6) W8(-2.8,-6) W9(-2,-6) W10(-1.2,-6) W11(-0.4,-6) W12(0.4,-6) W13(1.2,-6) W14(2,-6) W15(2.8,-6) W16(3.6,-6) W17(4.4,-6) W18(5.2,-6) W19(6,-6) W20(6.8,-6) W21(7.6,-6) W22(8.4,-6) Y1(-8.4,-6.8) Y2(-7.6,-6.8) Y3(-6.8,-6.8) Y4(-6,-6.8) Y5(-5.2,-6.8) Y6(-4.4,-6.8) Y7(-3.6,-6.8) Y8(-2.8,-6.8) Y9(-2,-6.8) Y10(-1.2,-6.8) Y11(-0.4,-6.8) Y12(0.4,-6.8) Y13(1.2,-6.8) Y14(2,-6.8) Y15(2.8,-6.8) Y16(3.6,-6.8) Y17(4.4,-6.8) Y18(5.2,-6.8) Y19(6,-6.8) Y20(6.8,-6.8) Y21(7.6,-6.8) Y22(8.4,-6.8)
  silkscreen extent -9.25,-9.1 9.1,9.25
ICC_P-WFBGA153_13X11P5_P050 [mm]
  round 0.23 smd mask+0: A1(-3.25,-3.25) A2(-3.25,-2.75) A3(-3.25,-2.25) A4(-3.25,-1.75) A5(-3.25,-1.25) A6(-3.25,-0.75) A7(-3.25,-0.25) A8(-3.25,0.25) A9(-3.25,0.75) A10(-3.25,1.25) A11(-3.25,1.75) A12(-3.25,2.25) A13(-3.25,2.75) A14(-3.25,3.25) B1(-2.75,-3.25) B2(-2.75,-2.75) B3(-2.75,-2.25) B4(-2.75,-1.75) B5(-2.75,-1.25) B6(-2.75,-0.75) B7(-2.75,-0.25) B8(-2.75,0.25) B9(-2.75,0.75) B10(-2.75,1.25) B11(-2.75,1.75) B12(-2.75,2.25) B13(-2.75,2.75) B14(-2.75,3.25) C1(-2.25,-3.25) C2(-2.25,-2.75) C3(-2.25,-2.25) C4(-2.25,-1.75) C5(-2.25,-1.25) C6(-2.25,-0.75) C7(-2.25,-0.25) C8(-2.25,0.25) C9(-2.25,0.75) C10(-2.25,1.25) C11(-2.25,1.75) C12(-2.25,2.25) C13(-2.25,2.75) C14(-2.25,3.25) D1(-1.75,-3.25) D2(-1.75,-2.75) D3(-1.75,-2.25) D4(-1.75,-1.75) D12(-1.75,2.25) D13(-1.75,2.75) D14(-1.75,3.25) E1(-1.25,-3.25) E2(-1.25,-2.75) E3(-1.25,-2.25) E5(-1.25,-1.25) E6(-1.25,-0.75) E7(-1.25,-0.25) E8(-1.25,0.25) E9(-1.25,0.75) E10(-1.25,1.25) E12(-1.25,2.25) E13(-1.25,2.75) E14(-1.25,3.25) F1(-0.75,-3.25) F2(-0.75,-2.75) F3(-0.75,-2.25) F5(-0.75,-1.25) F10(-0.75,1.25) F12(-0.75,2.25) F13(-0.75,2.75) F14(-0.75,3.25) G1(-0.25,-3.25) G2(-0.25,-2.75) G3(-0.25,-2.25) G5(-0.25,-1.25) G10(-0.25,1.25) G12(-0.25,2.25) G13(-0.25,2.75) G14(-0.25,3.25) H1(0.25,-3.25) H2(0.25,-2.75) H3(0.25,-2.25) H5(0.25,-1.25) H10(0.25,1.25) H12(0.25,2.25) H13(0.25,2.75) H14(0.25,3.25) J1(0.75,-3.25) J2(0.75,-2.75) J3(0.75,-2.25) J5(0.75,-1.25) J10(0.75,1.25) J12(0.75,2.25) J13(0.75,2.75) J14(0.75,3.25) K1(1.25,-3.25) K2(1.25,-2.75) K3(1.25,-2.25) K5(1.25,-1.25) K6(1.25,-0.75) K7(1.25,-0.25) K8(1.25,0.25) K9(1.25,0.75) K10(1.25,1.25) K12(1.25,2.25) K13(1.25,2.75) K14(1.25,3.25) L1(1.75,-3.25) L2(1.75,-2.75) L3(1.75,-2.25) L12(1.75,2.25) L13(1.75,2.75) L14(1.75,3.25) M1(2.25,-3.25) M2(2.25,-2.75) M3(2.25,-2.25) M4(2.25,-1.75) M5(2.25,-1.25) M6(2.25,-0.75) M7(2.25,-0.25) M8(2.25,0.25) M9(2.25,0.75) M10(2.25,1.25) M11(2.25,1.75) M12(2.25,2.25) M13(2.25,2.75) M14(2.25,3.25) N1(2.75,-3.25) N2(2.75,-2.75) N3(2.75,-2.25) N4(2.75,-1.75) N5(2.75,-1.25) N6(2.75,-0.75) N7(2.75,-0.25) N8(2.75,0.25) N9(2.75,0.75) N10(2.75,1.25) N11(2.75,1.75) N12(2.75,2.25) N13(2.75,2.75) N14(2.75,3.25) P1(3.25,-3.25) P2(3.25,-2.75) P3(3.25,-2.25) P4(3.25,-1.75) P5(3.25,-1.25) P6(3.25,-0.75) P7(3.25,-0.25) P8(3.25,0.25) P9(3.25,0.75) P10(3.25,1.25) P11(3.25,1.75) P12(3.25,2.25) P13(3.25,2.75) P14(3.25,3.25)
  silkscreen extent -6.78,-6.02 6.63,5.87
ICC_QFN56-EPAD_6P5X6P5_P040 [mm] "MCD-03000"
  rect 0.55x0.21 smd mask+0: 1(-3.245,2.6) 14(-3.245,-2.6) 29(3.245,-2.6) 42(3.245,2.6)
  rect 0.7x0.21 smd mask+0: 2(-3.17,2.2) 3(-3.17,1.8) 4(-3.17,1.4) 5(-3.17,1) 6(-3.17,0.6) 7(-3.17,0.2) 8(-3.17,-0.2) 9(-3.17,-0.6) 10(-3.17,-1) 11(-3.17,-1.4) 12(-3.17,-1.8) 13(-3.17,-2.2) 30(3.17,-2.2) 31(3.17,-1.8) 32(3.17,-1.4) 33(3.17,-1) 34(3.17,-0.6) 35(3.17,-0.2) 36(3.17,0.2) 37(3.17,0.6) 38(3.17,1) 39(3.17,1.4) 40(3.17,1.8) 41(3.17,2.2)
  rect 0.21x0.55 smd mask+0: 15(-2.6,-3.245) 28(2.6,-3.245) 43(2.6,3.245) 56(-2.6,3.245)
  rect 0.21x0.7 smd mask+0: 16(-2.2,-3.17) 17(-1.8,-3.17) 18(-1.4,-3.17) 19(-1,-3.17) 20(-0.6,-3.17) 21(-0.2,-3.17) 22(0.2,-3.17) 23(0.6,-3.17) 24(1,-3.17) 25(1.4,-3.17) 26(1.8,-3.17) 27(2.2,-3.17) 44(2.2,3.17) 45(1.8,3.17) 46(1.4,3.17) 47(1,3.17) 48(0.6,3.17) 49(0.2,3.17) 50(-0.2,3.17) 51(-0.6,3.17) 52(-1,3.17) 53(-1.4,3.17) 54(-1.8,3.17) 55(-2.2,3.17)
  rect 4.7x4.7 smd mask+0: 57(0,0)
  silkscreen extent -3.44,3 -3.01,3.42
IND_2016_MURATA_LQM2MPN2R2NG0 [mm]
  rect 0.8x1.8 smd mask+0: 1(-0.8,0) 2(0.8,0)
  silkscreen extent -0.28,-0.87 0.28,0.87
IND_2520_TOKO_DFE252012P [mm]
  rect 0.8x2 smd mask+0: 1(-1,0) 2(1,0)
  silkscreen extent -1.35,-1.12 1.35,1.12
LED_0603_OSRAM_LG-Q396-PS-35_GREEN_1A2K_H0P4 [mm]
  rect 0.8x0.8 smd mask+0: 1(-0.75,0) 2(0.75,0)
  silkscreen extent -0.85,-0.53 1.28,0.53
LINK200 [mm]
  rect 0.2x0.35 smd paste-10 mask+0: 1(0,-0.225) 2(0,0.225)
R0201_H0P23 [mm] "MCD-00702"
  rect 0.4x0.5 smd mask+0: 1(-0.3,0) 2(0.3,0)
R0402 [mm]
  rect 0.51x0.7 smd mask+0: 1(-0.45,0) 2(0.45,0)
R0603 [mm]
  rect 0.64x1 smd mask+0: 1(-0.7,0) 2(0.7,0)
  silkscreen extent -1.05,-0.58 1.05,0.58
SWI_WE_434121025816 [mm] "MCD-03492"
  rect 1.5x1.4 smd: 1(-3.25,0) 2(3.25,0)
  silkscreen extent -3,-1.95 3,1.95
TP_SMD_1MM [mm]
  round 1 smd paste-10 mask+0: 1(0,0)
  silkscreen extent -0.7,-0.7 0.7,0.7

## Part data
B2: library part MCD-03492, "Switch tactile, SPST-NO, 50mA, 12V, 6x3.8mm"
C1 C2 C3 C4 C5 C6 C7 C8 C9 C10 C11 C12 C13 C14 C15 C16 C17 C25 C31 C44 C45 C46 C47 C52 C53 C54 C55 C56 C57 C58 C59 C60 C67: library part MCD-02377, "Capacitor, MLCC, 1uF, 6.3V, X5R, +/-20%, 0201, T=0,3mm"
C18 C42: library part MCD-01796, "Capacitor, Tantalum, 100uF, 6V3, 40mR, +/-20%,  Type_B (3528 metric), T=1.9mm"
C19 C21 C152 C157 C186 C187 C193 C204 C206 C207: library part MCD-03139, "Capacitor, MLCC, 22uF, 10V, X5R, +/-20%, 0805, T=1,25mm"
C20 C29 C30 C32 C38 C184 C199: library part MCD-00099, "Capacitor, MLCC, 10uF, 10V, X5R, +/-10%, 0603, T=0,8mm"
C22 C23 C24 C26 C27 C28 C34 C35 C36 C37 C41 C183 C200 C202: library part MCD-00100, "Capacitor, MLCC, 22uF, 6V3, X5R, +/-20%, 0603, T=0,8mm"
C33: library part MCD-00011, "Capacitor, MLCC, 10nF, 16V, X7R, 10%, 0402, T=0.5mm"
C39 C40: library part MCD-03140, "Capacitor, MLCC, 10uF, 6.3V, X5R, +/-20%, 0402, T=0.5mm"
C43 C153 C154 C188: library part MCD-00095, "Capacitor, MLCC, 1uF, 25V, X5R, +/-10%, 0402, T=0.5mm"
C48 C49 C50 C51 C76 C77 C78 C80 C82 C83 C84 C93 C94 C95 C177 C179 C182 C211 C226 C238 C239 C245 C247 C255 C256 C257 C258 C259 C261 C262 C264 C276 C277 C279 C280 C282 C283 C284: library part MCD-00006, "Capacitor, MLCC, 100nF, 16V, X7R, +/-10%, 0402, T=0.5mm"
C61: library part MCD-01534, "Capacitor, MLCC, 4,7uF, 6V3, X5R, +/-20%, 0201, T=0.5mm"
C62 C63 C64 C65 C66 C68 C69 C70 C71 C72 C73 C74 C75 C89 C96 C97 C98 C212 C234 C275 C285: library part MCD-01535, "Capacitor, MLCC,100nF, 10V, X7R, +/-10%, 0201, T=0.3mm"
C79: library part MCD-02235, "Capacitor, MLCC, 2.2uF, 10V, X5R,+/-10%, 0201, T=0.5mm"
C81 C86 C90 C92: library part MCD-00674, "Capacitor, MLCC, 6.8pF, 50V, NPO, +-0.25pF, 0402, T=0.5mm"
C85 C99 C236 C278: library part MCD-01341, "Capacitor, MLCC, 10uF, 6V3, X5R, +/-20%, 0603, T=0,8mm"
C87: library part MCD-00006, "Capacitor,100nF,16V,X7R,10%,0402"
C88: library part MCD-01823, "Capacitor, MLCC, 2.2uF, 6V3, X5R,+/-10%, 0402, T=0.5mm"
C91 C141 C142 C156 C189 C190 C208 C209 C217: library part MCD-01356, "Capacitor, MLCC, 4.7uF, 6V3, X5R, +/-20%, 0402, T=0.5mm"
C155: library part MCD-02198, "Capacitor, MLCC, 10nF, 50V, X7R, +/-10%, 0402, T=0.5mm"
C178 C180 C181: library part MCD-02606, "Capacitor, MLCC, 2.2uF, 6.3V, X5R, +/-10%, 0402, T=0.5mm"
C254 C281: library part MCD-00099, "Capacitor, MLCC, 10uF, 10V, X5R, +/-10%, 0603, T=0.8mm"
CN12: library part MCD-00655, "Header 2 circuits, 1.25mm Pitch ,  Vertical, with Friction Lock"
D5: library part MCD-00034
D6: library part MCD-03280, "Diode, Schottky, Dual Common Cathode, 0V3, 300mA, 40V, SOT-23"
L1 L6: library part MCD-03143, "Inductor, 2.2uH, +/-20%, Itemp= 1700mA, Isat= 2400mA, 0R140, 0806, T=1mm"
L2 L4: library part MCD-03142, "Inductor, 0.68uH, +/-20%, Itemp= 3900mA, Isat= 5400mA, 0R031, 1008, T=1.2mm"
L3 L5 L7: library part MCD-03141, "Inductor, 0.68uH, +/-20%, Itemp= 3100mA, Isat= 4300mA, 0R043, 0806, T=1mm"
LD11: library part MCD-00588, "LED Green, 0603 SMD, Forward Voltage Typ=2V, Max=2.5V"
LNK1 LNK2 LNK4 LNK7 LNK8 LNK11: library part MCD-02777, "Track link on PCB 200um width for layout routing"
R2 R46 R57 R59 R60 R64 R75 R81 R267 R269 R286: library part MCD-00052, "Resistor,0R,0402,5%,1/16W"
R27 R37 R44 R49 R248 R252 R272: library part MCD-00053, "Resistor,10K,0402,1%,1/16W"
R63 R73 R262: library part MCD-02253, "Resistor,240R,0201,1%,1/20W"
R66: library part MCD-00058, "Resistor, 20R, 0402, +/-1%, 1/16W"
R67: library part MCD-00052, "Resistor, 0R, 0402, +/-5%, 1/16W"
R210: library part MCD-00441, "Resistor,270R,0402,1%,1/16W"
R249: library part MCD-00056, "Resistor, 0R, 0603, +/-5%, 1/10W"
R253 R254 R255 R256 R257 R258 R259 R263 R264 R265 R266 R268 R271 R273 R275 R276 R277 R278 R279 R280 R281 R282 R283 R284: library part MCD-00054, "Resistor, 56R, 0402, +/-1%, 1/16W"
R260 R261: library part MCD-00068, "Resistor,1K5,0402,1%,1/16W"
R270: library part MCD-01819, "Resistor,100R,0402,0,5%,1/16W,±100ppm/°C"
R300 R301 R302 R303: library part MCD-00061, "Resistor, 1K, 0402, +/-1%,1/16W"
TP9: library part MCD-00074, "Test Point 1mm"
U24: library part MCD-02799, "Memory, eMMC, 4GB, 15nm ,WFBGA , 153 pins"
U26: library part MCD-03000, "STPMIC2"
U27: library part MCD-02000, "MPU, ARM Cortex-A35 + M33 32-bit MPU, 808KB RAM, With Crypto"
U28: library part MCD-03523, "Memory, DDR4 SDRAM, 1V2, 16Gbit, FBGA96"
U29: library part MCD-03523, "Memory, DDR4 SDRAM, 1V2, 16Gbit, 1.6 GHz, FBGA96"
X1: library part MCD-01479, "Crystal, 32.768kHz, 6pF, +/-20ppm, 80K, 2.05x1.2mm"
X2: library part MCD-02344, "Crystal, 40MHz, 6pF, +/-20ppm, 80R, 1.6x1.2mm"

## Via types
v1: diameter 0.55, hole 0.35, Top Layer to Bottom Layer, 432 vias
v2: diameter 0.4, hole 0.2, Top Layer to Bottom Layer, tented both sides, 202 vias
v3: diameter 0.5, hole 0.2, Top Layer to Bottom Layer, 146 vias
v4: diameter 0.5, hole 0.25, Top Layer to Bottom Layer, 144 vias

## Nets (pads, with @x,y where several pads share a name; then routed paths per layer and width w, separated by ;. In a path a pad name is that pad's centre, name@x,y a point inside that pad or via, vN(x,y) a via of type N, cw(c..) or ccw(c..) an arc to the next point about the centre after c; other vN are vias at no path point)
1V8: C72.2 C89.2 C96.2 C97.2 C98.2 C152.2 C157.2 C178.2 C179.2 C193.2 C212.2 C275.2 C285.2 L1.2 LNK1.2 R37.2 R44.2 R49.2 R248.2 R267.2 R269.1 U24.C6 U24.M4 U24.N4 U24.P3 U24.P5 U27.C4 U27.C7 U27.F6 U27.F10 U27.G17 U27.J16 U27.K8 U27.L8 U27.U17 U27.W18 | length 110.6
  Top Layer w0.2: LNK1.2@60.6,84.348 v1(60.6,84.95) ; v2(87.6,79.6) U27.C4@88,79.2 v2(87.6,79.6) ; v2(89.2,77.2) U27.F6@89.6,76.8 ; U27.C7@90.4,79.2 90.415,79.185 90.415,79.02 v2(90.66,78.775) ; U27.L8@91.2,72.8 91.175,72.8 v2(90.8,73.175) 91.2,73.575 U27.K8@91.2,73.6 ; v2(91.624,77.173) 92.413,77.173 92.786,76.8 U27.F10@92.8,76.8 ; U27.J16@97.6,74.4 98,74.8 v2(98,76.375) 98.012,76.375 98.388,76 U27.G17@98.4,76 ; U27.U17@98.4,68 v2(98.8,67.6) ; v2(98.868,66.067) U27.W18@99.2,66.4 ; v1(102.23,91.5) R37.2@102.975,91.5 ; R44.2@103.1,85.528 103.125,85.503 v1(103.125,84.875) ; U24.C6@108.275,89.85 108.452,90.027 108.727,90.027 v1(108.775,90.075) ; v1(112.25,88.85) U24.M4@112.775,88.85 U24.N4@113.275,88.85 ; U24.P3@113.775,88.35 113.975,88.15 v1(114.35,88.15) ; U24.P5@113.775,89.35 114.005,89.58 114.23,89.58 v1(114.25,89.6) ; R49.2@114.625,83.685 v1(115.35,83.685)
  Top Layer w0.64: C152.2@59.5,84.95 v1(60.6,84.95) v1(61.28,84.95) 61.142,85.088 v1(61.142,94.8)
  Top Layer w0.8: L1.2@57.495,83.175 57.495,84.9 57.545,84.95 C157.2@57.65,84.95
  Top Layer w0.9: C193.2@55.8,84.95 C157.2@57.545,84.95 ; C157.2@57.65,84.95 C152.2@59.5,84.95
  Signal Layer 2 w0.2: 96.075,70.9 95.825,71.15 95.484,71.15 95.399,71.235 95.248,71.386 95.248,72.063 95.201,72.109 95.201,73.292 95.317,73.408 95.317,73.433 95.434,73.55 95.723,73.55 96.007,73.834 96.007,74.166 96.003,74.169 96.257,74.423 96.684,74.423 ; v2(98.868,66.067) v2@98.868,66.094
  Signal Layer 2 w0.3: v1(86.019,84.939) 92.721,84.939 97.371,80.289 97.371,77.004 v2(98,76.375) ; 96.075,70.9 96.075,69.048 96.075,69.014 96.339,68.75 97.65,68.75 v2(98.8,67.6) ; 96.684,74.423 97.65,75.389 97.65,76.018 v2@98,76.367 ; v2(98.8,67.6) 99.15,67.25 99.15,66.377 v2@98.868,66.094
  Signal Layer 2 w0.64: v1@60.6,84.955 v1@61.28,84.955 ; v1(61.28,84.95) 86.009,84.95 v1(86.019,84.939)
  Bottom Layer w0.17: C89.2@97.35,67.825 97.415,67.89 97.44,67.89 97.56,68.01 98.39,68.01 v2(98.8,67.6)
  Bottom Layer w0.2: R269.1@85.854,69.315 85.854,69.41 86.009,69.565 86.104,69.565 86.35,69.811 R267.2@86.35,70.375 ; R267.2@86.325,70.715 86.697,71.087 89.377,71.087 89.723,71.434 89.723,72.448 90.059,72.783 90.457,72.783 90.8,73.127 v2(90.8,73.175) ; v2(89.2,77.2) 89.458,76.942 89.458,75.927 89.985,75.4 89.985,73.99 v2(90.8,73.175) ; v2(90.66,78.775) 90.66,78.79 90.825,78.955 C97.2@90.825,79.375 ; C212.2@91.31,73.1 91.272,73.138 90.837,73.138 v2(90.8,73.175) ; C96.2@98.85,65.55 98.85,66.05 v2(98.868,66.067)
  Bottom Layer w0.3: C98.2@87.175,79.175 v2(87.6,79.6) ; C72.2@91.6,77.7 91.6,77.224 91.624,77.2 v2(91.624,77.173) ; C285.2@97.555,74.91 97.94,75.295 97.94,76.288 98,76.348 v2(98,76.375) ; R248.2@111.675,87.95 112.241,88.516 112.241,88.841 v1(112.25,88.85) ; C178.2@113.275,89.55 114.132,89.55 114.182,89.6 v1(114.25,89.6) ; v1(114.35,88.15) 114.418,88.15 114.543,88.025 C179.2@115.225,88.025
  Bottom Layer w0.4: C275.2@88.675,77.2 v2(89.2,77.2)
  other v1: 85.224,84.95 61.131,94.047
1V8_FB: LNK1.1 U26.35 | length 5.1
  Top Layer w0.15: U26.35@60.2,78.97 60.2,81.311 60.175,81.336 60.175,83.473 LNK1.1@60.6,83.898
3V3: C21.2 C154.2 C204.2 C206.2 C207.2 L7.2 U26.3 U26.53 | length 15.3
  Top Layer w0.15: v3(54.91,71.977) 55.262,72.329 55.262,73.465 56.197,74.4 U26.53@56.83,74.4 ; U26.53@56.62,74.369 56.919,74.369 U26.53@56.95,74.4
  Top Layer w0.21: 57.973,71.598 58.2,71.825 U26.3@58.2,72.63
  Top Layer w0.3: C154.2@56.975,69.175 C154.2@57,69.175 v3@57.585,69.175
  Top Layer w0.4: C154.2@57,69.175 57.014,69.189 57.014,69.685 57.46,70.131 57.46,71.085 57.973,71.598
  Top Layer w0.9: C206.2@45.087,70.323 C21.2@50.5,70.323 51.862,70.323 L7.2@51.887,70.298
  other v1: 44.687,68.823 45.412,68.823 46.137,68.823 44.687,69.498 45.412,69.498 46.137,69.498
  other v3: 57.61,69.175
